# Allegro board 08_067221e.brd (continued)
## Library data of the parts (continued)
U10 = ADMAX16823: User Part Number: UPN; Tolerance: N/A; alternate symbols: (TSSOP16_5X4_4_PAD2_85X2_85); part number: ADMAX16823_SM-MAX16823AUE+,E055203,TSSOP16_5X4_4_PAD2_85X2_85; tolerance: N/A
U11-U14 = ICT3902: Tolerance: N/A; User Part Number: UPN; alternate symbols: (LGA_CAV5_MEMS); part number: ICT3902_SM-MMICT3902-00-012,E056497,LGA_CAV5_MEMS; tolerance: N/A
U15 U21 = IC24XX512: Tolerance: N/A; User Part Number: UPN; alternate symbols: (SO8); part number: IC24XX512_SM-24AA512T-I/SN,E035973,SO8; tolerance: N/A
U16 = ADLT3502: User Part Number: UPN; Tolerance: N/A; alternate symbols: (DFN8_2X2_PAD1_37X0_64); part number: ADLT3502_SM-LT3502AEDC#TRMPBF,E035029,DFN8_2X2_PAD1_37X0_64; tolerance: N/A
U19 = ADP2360: Tolerance: N/A; User Part Number: UPN; alternate symbols: (DFN8_3X3_PAD2_44X1_6); part number: ADP2360_SM-ADP2360ACPZ,E019461,DFN8_3X3_PAD2_44X1_6; tolerance: N/A
U20 = ADMAX22503E: Tolerance: N/A; User Part Number: UPN; alternate symbols: (SO14NB-2); part number: ADMAX22503E_SM-MAX22503EASD+,E055928,SO14NB-2; tolerance: N/A
U28 = 7404_V6: User Part Number: UPN; Tolerance: N/A; alternate symbols: (SOT23-5L-2); part number: 7404_V6_SM-SN74LVC1G04DBVR,E030862,SOT23-5L-2; tolerance: N/A
Y1 = XTALOSC4P_V2: Tolerance: N/A; User Part Number: UPN; alternate symbols: (YSML126W98H47); part number: XTALOSC4P_V2_SM-24.576MEGHZ,E058822,YSML126W98H47; tolerance: N/A

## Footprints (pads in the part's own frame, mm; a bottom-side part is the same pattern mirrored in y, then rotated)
C0402
  rect 0.584x0.66 smd: 1(-0.5,0) 2(0.5,0)
C0603
  rect 0.94x0.991 smd: 1(-0.8,0) 2(0.8,0)
C0603#2
  rect 0.762x0.889 smd: 1(-0.7,0) 2(0.7,0)
C0805H53
  rect 1.295x1.6 smd: 1(-0.953,0) 2(0.953,0)
C0805H60
  rect 1.295x1.6 smd: 1(-0.953,0) 2(0.953,0)
C1206
  rect 1.143x1.803 smd: 1(-1.5,0) 2(1.5,0)
C1206H71
  rect 1.6x2.007 smd: 1(-1.397,0) 2(1.397,0)
C1210-2
  rect 1.092x2.057 smd: 1(-1.646,0) 2(1.646,0)
C1812H110
  rect 1.905x3.429 smd: 1(-1.956,0) 2(1.956,0)
CAPSML169W169H217
  rect 2.591x1.6 smd: N(1.796,0) P(-1.796,0)
CN3MN2510-6002RB
  rect 1.524x1.524 hole 1.016: 1(0,0)
  round 1.524 hole 1.016: 2(0,2.54) 3(2.54,0) 4(2.54,2.54) 5(5.08,0) 6(5.08,2.54) 7(7.62,0) 8(7.62,2.54) 9(10.16,0) 10(10.16,2.54)
CNBERG2X16H330LD36
  rect 1.651x1.651 hole 1.143: 1(0,0)
  round 1.651 hole 1.143: 2(0,2.54) 3(2.54,0) 4(2.54,2.54) 5(5.08,0) 6(5.08,2.54) 7(7.62,0) 8(7.62,2.54) 9(10.16,0) 10(10.16,2.54) 11(12.7,0) 12(12.7,2.54) 13(15.24,0) 14(15.24,2.54) 15(17.78,0) 16(17.78,2.54) 17(20.32,0) 18(20.32,2.54) 19(22.86,0) 20(22.86,2.54) 21(25.4,0) 22(25.4,2.54) 23(27.94,0) 24(27.94,2.54) 25(30.48,0) 26(30.48,2.54) 27(33.02,0) 28(33.02,2.54) 29(35.56,0) 30(35.56,2.54) 31(38.1,0) 32(38.1,2.54)
CNCLIFF_FCR684208R
  round 2.21 hole 1.702 unplated: (-0.26,5.1) (5.34,5.1)
  round 1.651 hole 1.143: (0,2.6) (5.08,2.6)
  rect 1.397x1.397 hole 0.889: 1(0,0)
  round 1.397 hole 0.889: 2(2.54,0) 3(5.08,0)
CNCLIFF_FCR684208T
  round 2.21 hole 1.702 unplated: (-0.26,5.1) (5.34,5.1)
  round 1.651 hole 1.143: (0,2.6) (5.08,2.6)
  rect 1.397x1.397 hole 0.889: 1(0,0)
  round 1.397 hole 0.889: 2(2.54,0) 3(5.08,0)
CNCUI-PJ-102A_SLOTPAD
  round 2.413 hole 1.905: 1(0,0) 2(6,0) 3(3,4.7)
CNCUIRCJ-01
  rect 2.21x2.21 hole 1.702: 1(0,0)
  round 3.175 hole 2.667: 2(-5,0) 3(0,4.5) 4(5,0)
CNCUISJ1-3525NG
  oval 1.295x2.007 hole 0.787x1.499: 1(0,0)
  oval 2.007x1.295 hole 1.499x0.787: 2(5,-5) 3(5,5) 4(5,-2.5) 5(5,2.5)
CNSAMTEC2X5H338LD36
  rect 1.651x1.651 hole 1.143: 1(0,0)
  round 1.651 hole 1.143: 2(0,2.54) 3(2.54,0) 4(2.54,2.54) 5(5.08,0) 6(5.08,2.54) 7(7.62,0) 8(7.62,2.54) 9(10.16,0) 10(10.16,2.54)
CNSAMTECLSS-150-01-X-DV-A
  round 1.016 hole 0.889 unplated: (-16.625,-1.1) (16.625,-1.1)
  rect 0.406x1.6 smd: 1(-15.557,1.8) 2(-15.557,-1.8) 3(-14.922,1.8) 4(-14.922,-1.8) 5(-14.287,1.8) 6(-14.287,-1.8) 7(-13.652,1.8) 8(-13.652,-1.8) 9(-13.018,1.8) 10(-13.018,-1.8) 11(-12.383,1.8) 12(-12.383,-1.8) 13(-11.748,1.8) 14(-11.748,-1.8) 15(-11.113,1.8) 16(-11.113,-1.8) 17(-10.477,1.8) 18(-10.477,-1.8) 19(-9.842,1.8) 20(-9.842,-1.8) 21(-9.207,1.8) 22(-9.207,-1.8) 23(-8.572,1.8) 24(-8.572,-1.8) 25(-7.938,1.8) 26(-7.938,-1.8) 27(-7.303,1.8) 28(-7.303,-1.8) 29(-6.668,1.8) 30(-6.668,-1.8) 31(-6.032,1.8) 32(-6.032,-1.8) 33(-5.397,1.8) 34(-5.397,-1.8) 35(-4.763,1.8) 36(-4.763,-1.8) 37(-4.128,1.8) 38(-4.128,-1.8) 39(-3.493,1.8) 40(-3.493,-1.8) 41(-2.857,1.8) 42(-2.857,-1.8) 43(-2.223,1.8) 44(-2.223,-1.8) 45(-1.587,1.8) 46(-1.587,-1.8) 47(-0.953,1.8) 48(-0.953,-1.8) 49(-0.318,1.8) 50(-0.318,-1.8) 51(0.318,1.8) 52(0.318,-1.8) 53(0.953,1.8) 54(0.953,-1.8) 55(1.587,1.8) 56(1.587,-1.8) 57(2.223,1.8) 58(2.223,-1.8) 59(2.857,1.8) 60(2.857,-1.8) 61(3.493,1.8) 62(3.493,-1.8) 63(4.128,1.8) 64(4.128,-1.8) 65(4.763,1.8) 66(4.763,-1.8) 67(5.397,1.8) 68(5.397,-1.8) 69(6.032,1.8) 70(6.032,-1.8) 71(6.668,1.8) 72(6.668,-1.8) 73(7.303,1.8) 74(7.303,-1.8) 75(7.938,1.8) 76(7.938,-1.8) 77(8.572,1.8) 78(8.572,-1.8) 79(9.207,1.8) 80(9.207,-1.8) 81(9.842,1.8) 82(9.842,-1.8) 83(10.477,1.8) 84(10.477,-1.8) 85(11.113,1.8) 86(11.113,-1.8) 87(11.748,1.8) 88(11.748,-1.8) 89(12.383,1.8) 90(12.383,-1.8) 91(13.018,1.8) 92(13.018,-1.8) 93(13.652,1.8) 94(13.652,-1.8) 95(14.287,1.8) 96(14.287,-1.8) 97(14.922,1.8) 98(14.922,-1.8) 99(15.557,1.8) 100(15.557,-1.8)
CNTHMHDR1X2L200W98H343
  rect 1.651x1.651 hole 1.143: 1(0,0)
  round 1.651 hole 1.143: 2(2.54,0)
CNTHMHDR1X3L300W98H343
  rect 1.651x1.651 hole 1.143: 1(0,0)
  round 1.651 hole 1.143: 2(2.54,0) 3(5.08,0)
CNTHMHDR1X4L400W98H343
  rect 1.651x1.651 hole 1.143: 1(0,0)
  round 1.651 hole 1.143: 2(2.54,0) 3(5.08,0) 4(7.62,0)
CNWEIDMULLER171602
  rect 1.905x1.905 hole 1.397: 1(0,0)
  round 1.905 hole 1.397: 2(5.08,0)
CPLSMSQ260H240
  rect 3.302x1.651 smd: N(-2.601,0) P(2.601,0)
CPLSMSQ512H650
  rect 5.588x2.362 smd: N(4.85,0) P(-4.85,0)
DFN8_2X2_PAD1_37X0_64
  oval 0.254x0.737 smd: 1(-0.675,-0.888) 2(-0.225,-0.888) 3(0.225,-0.888) 4(0.675,-0.888) 5(0.675,0.888) 6(0.225,0.888) 7(-0.225,0.888) 8(-0.675,0.888)
  rect 1.372x0.635 smd: PAD(0,0)
DFN8_3X3_PAD2_44X1_6
  oval 0.356x0.787 smd: 1(-0.975,-1.5) 2(-0.325,-1.5) 3(0.325,-1.5) 4(0.975,-1.5) 5(0.975,1.5) 6(0.325,1.5) 7(-0.325,1.5) 8(-0.975,1.5)
  rect 2.438x1.6 smd: PAD(0,0)
DFN10_3X3_PAD2_38X1_65_05-08-1699
  oval 0.254x0.889 smd: 1(-1,-1.555) 2(-0.5,-1.555) 3(0,-1.555) 4(0.5,-1.555) 5(1,-1.555) 6(1,1.555) 7(0.5,1.555) 8(0,1.555) 9(-0.5,1.555) 10(-1,1.555)
  rect 2.388x1.651 smd: 11(0,0)
FLSML154W98H98
  rect 1.041x0.61 smd: 1(-1.521,0.505) 2(-1.521,-0.505) 3(1.521,-0.505) 4(1.521,0.505)
L0402-3
  rect 0.457x0.508 smd: 1(-0.479,0) 2(0.479,0)
L0603
  rect 0.94x0.991 smd: 1(-0.8,0) 2(0.8,0)
L0603-2
  rect 0.991x1.245 smd: 1(-0.787,0) 2(0.787,0)
L0805H57
  rect 0.914x1.372 smd: 1(-0.902,0) 2(0.902,0)
LED0603
  rect 0.965x0.762 smd: A(0.8,0) C(-0.8,0)
LED0805
  rect 1.245x1.092 smd: A(1.172,0) C(-1.172,0)
LEDCMD28-21B
  rect 1.524x0.762 smd: A(1.778,0)
  rect 1.524x1.016 smd: C(-1.778,0)
LEDSMSQ134H114
  rect 0.711x1.6 smd: 1(-1.061,-1.7) 2(0,-1.7) 3(1.061,-1.7) 4(1.061,1.7) 5(0,1.7) 6(-1.061,1.7)
LGA_CAV5_MEMS
  round 0.635 hole 0.508 unplated: (0.71,0)
  rect 0.533x0.737 smd: 1(-1.364,-0.837) 2(-0.542,-0.837) 4(-0.542,0.837) 5(-1.364,0.837)
  custom 0.407x0.407 smd: 3(0.71,-0.65)
LQFP64
  rect 0.254x1.651 smd: 1(-3.75,-5.675) 2(-3.25,-5.675) 3(-2.75,-5.675) 4(-2.25,-5.675) 5(-1.75,-5.675) 6(-1.25,-5.675) 7(-0.75,-5.675) 8(-0.25,-5.675) 9(0.25,-5.675) 10(0.75,-5.675) 11(1.25,-5.675) 12(1.75,-5.675) 13(2.25,-5.675) 14(2.75,-5.675) 15(3.25,-5.675) 16(3.75,-5.675) 33(3.75,5.675) 34(3.25,5.675) 35(2.75,5.675) 36(2.25,5.675) 37(1.75,5.675) 38(1.25,5.675) 39(0.75,5.675) 40(0.25,5.675) 41(-0.25,5.675) 42(-0.75,5.675) 43(-1.25,5.675) 44(-1.75,5.675) 45(-2.25,5.675) 46(-2.75,5.675) 47(-3.25,5.675) 48(-3.75,5.675)
  rect 1.651x0.254 smd: 17(5.675,-3.75) 18(5.675,-3.25) 19(5.675,-2.75) 20(5.675,-2.25) 21(5.675,-1.75) 22(5.675,-1.25) 23(5.675,-0.75) 24(5.675,-0.25) 25(5.675,0.25) 26(5.675,0.75) 27(5.675,1.25) 28(5.675,1.75) 29(5.675,2.25) 30(5.675,2.75) 31(5.675,3.25) 32(5.675,3.75) 49(-5.675,3.75) 50(-5.675,3.25) 51(-5.675,2.75) 52(-5.675,2.25) 53(-5.675,1.75) 54(-5.675,1.25) 55(-5.675,0.75) 56(-5.675,0.25) 57(-5.675,-0.25) 58(-5.675,-0.75) 59(-5.675,-1.25) 60(-5.675,-1.75) 61(-5.675,-2.25) 62(-5.675,-2.75) 63(-5.675,-3.25) 64(-5.675,-3.75)
LSML213W201H59
  rect 1.397x2.794 smd: 1(-2.199,0) 2(2.199,0)
LSMSQ157H122
  rect 0.965x3.708 smd: 1(-1.181,0) 2(1.181,0)
LSMSQ189H118_A
  custom 0.502x0.502 smd: 1(-2.255,0) 2(2.255,0)
LXT0805
  rect 1.194x1.194 smd: A(1.041,0) C(-1.041,0)
MRJE73-188-00XXX
  round 2.311 hole 1.803 unplated: (-2.17,-0.33) (9.31,-0.33)
  rect 1.397x1.397 hole 0.889: 1(0,0)
  round 1.397 hole 0.889: 2(1.02,-1.78) 3(2.04,0) 4(3.06,-1.78) 5(4.08,0) 6(5.1,-1.78) 7(6.12,0) 8(7.14,-1.78)
  round 1.6 hole 1.092: 9(-3.44,3.27) 10(-0.9,3.27) 11(8.04,3.27) 12(10.58,3.27)
  oval 1.295x2.515 hole 0.787x2.007: 13(-4.43,-4.68) 14(11.57,-4.68)
POWERDI5060-8
  rect 0.61x1.27 smd: 1(-1.905,-2.67) 2(-0.635,-2.67) 3(0.635,-2.67) 4(1.905,-2.67)
  custom 1.13x1.13 smd: 5(1.905,2.797)
  round 0.127 smd: 6(0.635,2.67) 7(-0.635,2.67) 8(-1.905,2.67)
QFN48_7X7_PAD4_1X4_1
  round 2.718 hole 1.702 unplated: (-4.863,4.863) (-4.863,-4.863) (4.863,4.863) (4.863,-4.863)
  round 1.092 hole 0.838 unplated: (-2.863,4.863) (1.863,-4.863)
  oval 0.305x0.889 smd: 1(-2.75,-3.2) 2(-2.25,-3.2) 3(-1.75,-3.2) 4(-1.25,-3.2) 5(-0.75,-3.2) 6(-0.25,-3.2) 7(0.25,-3.2) 8(0.75,-3.2) 9(1.25,-3.2) 10(1.75,-3.2) 11(2.25,-3.2) 12(2.75,-3.2) 25(2.75,3.7) 26(2.25,3.7) 27(1.75,3.7) 28(1.25,3.7) 29(0.75,3.7) 30(0.25,3.7) 31(-0.25,3.7) 32(-0.75,3.7) 33(-1.25,3.7) 34(-1.75,3.7) 35(-2.25,3.7) 36(-2.75,3.7)
  oval 0.889x0.305 smd: 13(3.45,-2.5) 14(3.45,-2) 15(3.45,-1.5) 16(3.45,-1) 17(3.45,-0.5) 18(3.45,0) 19(3.45,0.5) 20(3.45,1) 21(3.45,1.5) 22(3.45,2) 23(3.45,2.5) 24(3.45,3) 37(-3.45,3) 38(-3.45,2.5) 39(-3.45,2) 40(-3.45,1.5) 41(-3.45,1) 42(-3.45,0.5) 43(-3.45,0) 44(-3.45,-0.5) 45(-3.45,-1) 46(-3.45,-1.5) 47(-3.45,-2) 48(-3.45,-2.5)
  rect 4.089x4.089 smd: PAD(0,0.25)
QFN72_10X10_PAD5_3X5_3
  oval 0.305x0.838 smd: 1(-4.25,-4.95) 2(-3.75,-4.95) 3(-3.25,-4.95) 4(-2.75,-4.95) 5(-2.25,-4.95) 6(-1.75,-4.95) 7(-1.25,-4.95) 8(-0.75,-4.95) 9(-0.25,-4.95) 10(0.25,-4.95) 11(0.75,-4.95) 12(1.25,-4.95) 13(1.75,-4.95) 14(2.25,-4.95) 15(2.75,-4.95) 16(3.25,-4.95) 17(3.75,-4.95) 18(4.25,-4.95) 37(4.25,4.95) 38(3.75,4.95) 39(3.25,4.95) 40(2.75,4.95) 41(2.25,4.95) 42(1.75,4.95) 43(1.25,4.95) 44(0.75,4.95) 45(0.25,4.95) 46(-0.25,4.95) 47(-0.75,4.95) 48(-1.25,4.95) 49(-1.75,4.95) 50(-2.25,4.95) 51(-2.75,4.95) 52(-3.25,4.95) 53(-3.75,4.95) 54(-4.25,4.95)
  oval 0.838x0.305 smd: 19(4.95,-4.25) 20(4.95,-3.75) 21(4.95,-3.25) 22(4.95,-2.75) 23(4.95,-2.25) 24(4.95,-1.75) 25(4.95,-1.25) 26(4.95,-0.75) 27(4.95,-0.25) 28(4.95,0.25) 29(4.95,0.75) 30(4.95,1.25) 31(4.95,1.75) 32(4.95,2.25) 33(4.95,2.75) 34(4.95,3.25) 35(4.95,3.75) 36(4.95,4.25) 55(-4.95,4.25) 56(-4.95,3.75) 57(-4.95,3.25) 58(-4.95,2.75) 59(-4.95,2.25) 60(-4.95,1.75) 61(-4.95,1.25) 62(-4.95,0.75) 63(-4.95,0.25) 64(-4.95,-0.25) 65(-4.95,-0.75) 66(-4.95,-1.25) 67(-4.95,-1.75) 68(-4.95,-2.25) 69(-4.95,-2.75) 70(-4.95,-3.25) 71(-4.95,-3.75) 72(-4.95,-4.25)
  rect 5.309x5.309 smd: PAD(0,0)
R0402
  rect 0.635x0.737 smd: 1(-0.5,0) 2(0.5,0)
R0603
  rect 0.787x0.991 smd: 1(-0.85,0) 2(0.85,0)
R0805
  rect 1.041x1.397 smd: 1(-0.95,0) 2(0.95,0)
R1206
  rect 1.041x1.753 smd: 1(-1.5,0) 2(1.5,0)
R1206-2
  rect 1.397x1.803 smd: 1(-1.298,0) 2(1.298,0)
R1210
  rect 1.575x2.692 smd: 1(-1.397,0) 2(1.397,0)
SC70-5
  rect 0.406x0.813 smd: 1(-0.65,-0.89) 2(0,-0.89) 3(0.65,-0.89) 4(0.65,0.89) 5(-0.65,0.89)
SMA
  rect 2.032x2.032 smd: A(1.994,0) C(-1.994,0)
SO4H96
  rect 0.66x1.956 smd: 1(-0.635,-3.083) 2(0.635,-3.083) 3(0.635,3.083) 4(-0.635,3.083)
SO8
  rect 0.61x2.184 smd: 1(-1.905,-2.54) 2(-0.635,-2.54) 3(0.635,-2.54) 4(1.905,-2.54) 5(1.905,2.54) 6(0.635,2.54) 7(-0.635,2.54) 8(-1.905,2.54)
SO8NB-5
  rect 0.635x1.829 smd: 1(-1.905,-2.591) 2(-0.635,-2.591) 3(0.635,-2.591) 4(1.905,-2.591) 5(1.905,2.591) 6(0.635,2.591) 7(-0.635,2.591) 8(-1.905,2.591)
SO14NB-2
  rect 0.635x1.829 smd: 1(-3.81,-2.591) 2(-2.54,-2.591) 3(-1.27,-2.591) 4(0,-2.591) 5(1.27,-2.591) 6(2.54,-2.591) 7(3.81,-2.591) 8(3.81,2.591) 9(2.54,2.591) 10(1.27,2.591) 11(0,2.591) 12(-1.27,2.591) 13(-2.54,2.591) 14(-3.81,2.591)
SO16NB-2
  rect 0.635x1.829 smd: 1(-4.445,-2.591) 2(-3.175,-2.591) 3(-1.905,-2.591) 4(-0.635,-2.591) 5(0.635,-2.591) 6(1.905,-2.591) 7(3.175,-2.591) 8(4.445,-2.591) 9(4.445,2.591) 10(3.175,2.591) 11(1.905,2.591) 12(0.635,2.591) 13(-0.635,2.591) 14(-1.905,2.591) 15(-3.175,2.591) 16(-4.445,2.591)
SOD123F
  rect 1.194x1.194 smd: A(1.403,0) C(-1.403,0)
SOD123FL
  rect 0.914x1.219 smd: A(1.638,0) C(-1.638,0)
SOT23-5L-2
  rect 0.61x1.194 smd: 1(-0.95,-1.15) 2(0,-1.15) 3(0.95,-1.15) 4(0.95,1.15) 5(-0.95,1.15)
SOT143A
  rect 1.092x1.27 smd: 1(-0.76,-1)
  rect 0.711x1.27 smd: 2(0.96,-1) 3(0.96,1) 4(-0.96,1)
SOT363H43
  rect 0.432x0.61 smd: 1(-0.65,-0.95) 2(0,-0.95) 3(0.65,-0.95) 4(0.65,0.95) 5(0,0.95) 6(-0.65,0.95)
SWSML165W110H75-G
  rect 0.889x0.991 smd: 1(-2.044,-0.795) 2(-2.044,0.795) 3(2.044,0.795) 4(2.044,-0.795)
  rect 1.702x0.559 smd: 5(0,-1.439)
SWSML354W142H217
  rect 1.194x2.515 smd: 1(-2.489,-2.743) 2(0,-2.743) 3(2.489,-2.743) 4(-2.489,2.743) 5(0,2.743) 6(2.489,2.743)
TO252
  rect 1.6x2.997 smd: 1(-2.3,-4.063) 3(2.3,-4.063)
  rect 6.706x6.706 smd: 2(0,2.589)
TPC65D45
  round 1.651 hole 1.143: 1(0,0)
TSML185W127H114_A
  rect 1.194x0.406 smd: 1(-1.99,-1.35) 2(-1.99,-0.7) 6(1.99,0.7) 7(1.99,1.35)
  custom 0.108x0.108 smd: 3(-2.371,1.35) 4(-1.606,1.35)
  rect 1.194x0.508 smd: 5(1.99,-1.305)
TSML387W323H220
  rect 1.016x2.54 smd: 1(-3.01,-5.08) 2(-1.003,-5.08) 3(1.003,-5.08) 4(3.01,-5.08) 5(3.01,5.08) 6(1.003,5.08) 7(-1.003,5.08) 8(-3.01,5.08)
TSSOP16_5X4_4_PAD2_85X2_85
  rect 0.381x1.27 smd: 1(-2.275,-2.82) 2(-1.625,-2.82) 3(-0.975,-2.82) 4(-0.325,-2.82) 5(0.325,-2.82) 6(0.975,-2.82) 7(1.625,-2.82) 8(2.275,-2.82) 9(2.275,2.82) 10(1.625,2.82) 11(0.975,2.82) 12(0.325,2.82) 13(-0.325,2.82) 14(-0.975,2.82) 15(-1.625,2.82) 16(-2.275,2.82)
  rect 2.845x2.845 smd: PAD(0,0)
unnamed#2
  round 4.445 hole 3.175 unplated: (0,0)
YSML126W98H47
  rect 1.397x1.194 smd: 1(-1.2,-0.95) 2(1.2,-0.95) 3(1.2,0.95) 4(-1.2,0.95)

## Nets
DGND: C1.1 C2.1 C3.1 C4.2(N2) C5.1 C6.1 C7.1 C8.1 C9.1 C10.1 C11.1 C12.1 C13.1 C14.1 C15.1 C16.1 C17.1 C18.1 C20.1 C21.1 C22.1 C23.2(N2) C24.1 C25.1 C26.1 C27.1 C28.1 C29.1 C31.1 C32.1 C33.1 C34.1 C35.2(N2) C36.1 C37.1 C38.1 C39.2(N2) C40.1 C41.2(N2) C42.1 C43.1 C46.1 C47.N(N2) C48.1 C49.1 C50.2(N2) C51.2(N2) C52.1 C55.1 C56.1 C57.1 C59.1 C61.1 C62.1 C64.2(N2) C65.1 C66.1 C67.2(N2) C69.1 C71.1 C72.2(N2) C73.1 C74.1 C75.1 C76.1 C77.1 C78.1 C79.1 C80.2(N2) C81.1 C82.1 C83.1 C84.1 C85.1 C87.1 C88.1 C89.1 C92.1 C93.1 C94.2(N2) C95.1 C96.1 C97.1 C100.1 C101.1 C102.1 C103.N(N2) C104.N(N2) C105.1 C106.1 C107.1 C108.1 C109.1 C110.1 C111.1 C112.1 C114.1 C116.2(N2) C118.1 C119.1 C120.1 C121.1 C122.1 C123.1 C124.1 C125.1 C126.1 C127.1 C128.1 C129.1 C131.1 C132.N(N2) C133.1 C135.1 C136.1 C137.1 C138.1 C140.1 C141.2(N2) C145.1 C146.1 C148.2(N2) C149.1 C150.2(N2) C151.2(N2) C152.2(N2) C153.1 C154.1 C156.1 C159.1 C161.1 C162.1 C163.1 C165.1 C168.1 C169.2(N2) C170.2(N2) C171.2(N2) C172.1 C173.1 C175.1 C176.1 C177.1 C178.1 C179.1 D3.A(P) D4.A(P) D8.1 D8.4 D9.1 D9.4 D10.A(P) DS2.C DS3.C DS4.C DS5.C DS7.C DS8.C DS9.C DS10.C DS11.C L6.1 P1.2 P1.3(N3) P2.2(N2) P4.2 P6.1 P8.9(N9) P8.10 P10.1 P10.6 P10.8 P10.13 P10.14(SH2) P15.2 P15.4 P15.6 P15.8 P15.10 P15.12 P15.14 P15.16 P15.18(N9) P15.20 P15.22 P15.24 P15.26 P15.28 P15.30 P15.32 P28.1 P29.1 P30.10 P32.1 P32.2 P32.5 P32.6 P32.9 P32.10 P32.13 P32.14 P32.17 P32.18(N9) P32.21 P32.22 P32.25 P32.26 P32.29 P32.30 P32.33 P32.34 P32.37 P32.38 P32.41 P32.42 P32.45 P32.46 P32.49 P32.50 P32.53 P32.54 P32.57 P32.58 P32.61 P32.62 P32.65 P32.66 P32.69 P32.70 P32.73 P32.74 P32.77 P32.78 P32.81 P32.82 P32.85 P32.89 P32.90 P32.91 P32.92 P32.94 R16.1 R21.1 R23.1 R24.1 R28.2(N2) R30.1 R31.1 R31.2(N2) R42.1 R72.1 R73.1 R80.2(N2) R82.2(N2) R85.2(N2) R93.1 R96.1 R96.2(N2) R110.1 R112.1 R112.2(N2) R128.1 R133.1 R135.1 R143.1 R144.1 R145.1 R146.1 R147.1 R149.1 R150.1 R151.1 R152.1 R153.1 R156.1 R159.1 R163.1 R164.1 R168.2(N2) R170.1 R176.2(N2) R178.1 R179.1 R184.1 R190.1 R215.1 R216.1 R244.1 R246.1 R248.1 R249.2(N2) R250.1 SW1.1 SW1.4 SW1.5(N5) T2.6 T2.7 T3.6 T3.7 TP2.1(N1) TP9.1(N1) TP12.1(N1) TP14.1(N1) TP21.1(N1) U1.3 U2.1 U3.5 U3.11 U4.1 U4.3 U5.4(-VS) U6.1 U6.6 U6.14 U6.17 U6.19 U6.25 U6.36 U6.37 U6.54 U6.55 U6.72 U6.PAD U7.1 U7.4 U7.16 U7.23(VSUPPLY) U7.24 U7.25 U7.33 U7.44 U7.46 U7.48 U8.8 U9.1 U9.4 U9.10 U9.20 U9.26(VSS) U9.30 U9.32 U9.38 U9.44 U9.PAD U10.12 U10.PAD U11.3 U12.2 U12.3 U13.3 U14.2 U14.3 U15.4 U16.5 U16.PAD U17.4(-VS) U18.4(-VS) U19.6 U19.PAD U20.3 U20.6 U20.7 U21.4 U24.3 U25.3 U26.3 U27.3 U28.3 Y1.2
GND_ISO: C99.1 C102.2(N2) P22.1 P22.6 P22.8 R65.1 R247.2(N2)
GND_SHIELD_A: C99.2(N2) P22.13 P22.14(SH2) TP4.1(N1)
VDD_3V3: C1.2(N2) C4.1 C5.2(N2) C26.2(N2) C27.2(N2) C56.2(N2) C60.1 C66.2(N2) C67.1 C82.2(N2) C94.1 C95.2(N2) C97.2(N2) C107.2(N2) C108.2(N2) C109.2(N2) C110.2(N2) C111.2(N2) C119.2(N2) C124.2(N2) C129.2(N2) C145.2(N2) C146.2(N2) C154.2(N2) C156.2(N2) C159.2(N2) C163.2(N2) C169.1 C170.1 C171.1 C172.2(N2) C175.2(N2) C176.2(N2) C179.2(N2) D8.2 D8.5(C1) D9.2 D9.5(C1) DS1.A(P) E1.1 E2.1 E6.1 E9.2(N2) E12.2(N2) E16.2(N2) E18.2(N2) JP47.1 P4.3 P6.2 P8.7 Q3.3(E) R2.1 R5.1 R9.1 R12.2(N2) R15.2(N2) R19.2(N2) R22.2(N2) R26.2(N2) R33.2(N2) R39.2(N2) R53.2(N2) R74.2(N2) R95.2(N2) R101.1 R107.1 R115.2(N2) R117.1 R118.1 R119.1 R122.2(N2) R126.2(N2) R137.2(N2) R139.2(N2) R142.2(N2) R148.2(N2) R161.2(N2) R166.2(N2) R174.2(N2) R175.2(N2) R180.2(N2) R185.2(N2) R186.2(N2) R187.1 R231.1 R238.2(N2) R243.2(N2) TP24.1(N1) U1.5 U2.4(VCC) U4.5(VCC) U5.8 U6.2 U6.18 U6.38 U6.56 U7.5 U7.17 U7.32 U7.45 U7.51 U7.62 U9.46 U15.8 U17.8 U18.8 U20.4 U20.13 U20.14 U24.5 U25.5 U26.5(VCC) U27.5(VCC) U28.5(VCC) Y1.4(VDD)
VDD_5V: C29.2(N2) C122.2(N2) D2.C D10.C L1.2(N2) P10.9 R170.2(N2) TP3.1(N1)
VDD_5V_BPORT: C120.2(N2) D2.A(P) E3.2(N2) R36.2(N2) R165.2(N2)
1452_RESET: C88.2(N2) R6.1 R107.2(N2) U6.24
AD243X_ADR1_SS: P15.23 P32.79 R100.1 R195.1
AD243X_AN: C30.2(N2) L2.2(N2) L4.1 U9.28
AD243X_AP: C30.1 L3.1 L5.1 U9.29
AD243X_BCLK: C10.2(N2) C151.1 JP1.4(N4) P15.1 P32.3 R45.2(N2) R62.2(N2) R172.2(N2) R241.1
AD243X_BCM: C13.2(N2) C14.2(N2) U9.35
AD243X_BN: C45.1 L9.1 L11.1 U9.34
AD243X_BP: C45.2(N2) L8.2(N2) L10.1 U9.33
AD243X_DRX0: C11.2(N2) JP6.1 P15.7 P32.11 R47.2(N2) R57.2(N2)
AD243X_DRX1: C12.2(N2) JP9.1 P15.9 P32.15 R48.2(N2)
AD243X_GPIO7: JP1.2 R14.1 R189.1 U4.2
AD243X_IOVDD: C22.2(N2) C40.2(N2) E1.2(N2) R7.2(N2) TP10.1(N1) U9.11 U9.21
AD243X_IRQ: P15.29 P32.59 R38.2(N2) R69.1 R118.2(N2) U9.24
AD243X_ISENSEP: Q4.5 Q4.6 Q4.7 Q4.8 R182.1 U9.42
AD243X_MISO: R86.1 R232.1
AD243X_MISO_SW: P15.19 P32.63 R92.1 R120.1
AD243X_MOSI: R97.1 R223.1
AD243X_MOSI_SW: P15.21 P32.67 R11.1 R111.1
AD243X_RESET: C173.2(N2) P23.1(N1) R3.1 R7.1 U9.25
AD243X_SCK: R106.1 R235.1
AD243X_SCK_SW: P15.17 P32.71 R113.1 R199.1
AD243X_SCL: P15.25 R35.2(N2) R70.2(N2) R122.1 U9.16
AD243X_SDA: P15.27 R55.2(N2) R126.1 R203.2(N2) U9.15
AD243X_SIO2: C141.1 P15.11 P32.19 R34.2(N2) R68.1 R81.1 R84.2(N2) R98.1
AD243X_SIO3: C64.1 P15.13 P32.23 R67.1 R114.1
AD243X_SIO4: C71.2(N2) P15.15 P32.27 R66.1 R121.1 R171.2(N2)
AD243X_SWP: C174.2(N2) Q4.4 U9.41
AD243X_SYNC: C9.2(N2) C152.1 P15.3 P32.7 R44.2(N2) R63.2(N2) R173.2(N2) R240.1
AD243X_VBUS: C46.2(N2) C101.2(N2) C103.P C104.P C114.2(N2) C132.P D5.C E11.2(N2) R18.2(N2) R32.2(N2) R154.1 R162.2(N2) R182.2(N2) TP13.1(N1) TP25.1(N1) U3.8(VOUT) U9.43 U16.1(VIN) U19.8(VIN)
AD243X_VOUT1: C123.2(N2) C126.2(N2) C128.2(N2) R169.2(N2) TP11.1(N1) U9.2 U9.3 U9.47 U9.48
AD243X_VSENSEP: R181.1 U9.40
AD1937_ADR0: R142.1 R143.2(N2) U7.30
AD1937_ADR1: R185.1 R190.2(N2) U7.35
AD1937_ASDATA1: R57.1 R71.1 R105.2(N2) TP8.1(N1)
AD1937_BCLK: C17.2(N2) R51.2(N2) R58.1 R87.1 R172.1
AD1937_CM: C83.2(N2) C112.2(N2) C137.2(N2) C138.2(N2) R43.2(N2) R60.2(N2) R61.2(N2) R124.2(N2) U7.52 U17.3 U17.5 U18.3 U18.5
AD1937_DSDATA1: C18.2(N2) R52.2(N2) R104.1 R171.1 TP7.1(N1)
AD1937_MCLKI: R91.1 R94.1 U7.2
AD1937_RESET: C162.2(N2) R134.1 R187.2(N2) U7.14
AD1937_SYNC: C16.2(N2) R50.2(N2) R59.1 R173.1 R183.1
ADAU1452_AUXADC0: P8.1 U6.8
ADAU1452_AUXADC1: P8.2 U6.9
ADAU1452_AUXADC2: P8.3 U6.10
ADAU1452_AUXADC3: P8.4 U6.11
ADAU1452_AUXADC4: P8.5 U6.12
ADAU1452_AUXADC5: P8.6 U6.13
ADAU1452_CLKOUT: C125.2(N2) R88.2(N2) R94.2(N2) TP18.1(N1)
ADAU1452_MP6: R95.1 U6.45 U25.1
ADAU1452_MP11: P8.8 U6.61
ADAU1452_SCL: R25.2(N2) R53.1 R79.2(N2) R132.2(N2) U27.2
ADAU1452_SDA: R29.2(N2) R39.1 R77.2(N2) R138.2(N2) U26.2
ADAU1452_SELFBOOT: JP2.2(N2) R93.2(N2) U6.34 U25.2
ADAU1452_SPDIFIN: R127.2(N2) R193.1 R226.2(N2)
ADAU1452_SPDIFIN_OPT: C177.2(N2) R103.2(N2) R119.2(N2) R127.1
ADAU1452_SPDIFIN_RCA: R226.1 U20.2
ADAU1452_SPDIFOUT: R116.2(N2) R227.2(N2) R228.2(N2)
ADAU1452_SPDIFOUT_OPT: C178.2(N2) P6.3(VIN) R227.1
ADAU1452_SPDIFOUT_RCA: R228.1 U20.5
ADC1LN: C133.2(N2) C134.2(N2) C142.2(N2) U7.54
ADC1LP: C134.1 C135.2(N2) C143.2(N2) U7.53
ADC1RN: C139.2(N2) C140.2(N2) C147.2(N2) U7.56
ADC1RP: C136.2(N2) C139.1 C144.2(N2) U7.55
ADP2360_EN: R154.2(N2) R159.2(N2) U19.1
ADP2360_PG: JP1.1 R125.2(N2) R161.1 U19.2
ADR1/SPISS0: JP42.1 R89.1 R177.1
ADR2/IO2/MCLK: JP38.3(N3) P15.31 P32.47 R12.1 R21.2(N2) R49.2(N2) R91.2(N2) R140.2(N2) R242.1
BCLK_IN0: R62.1 U6.57
DAC1LN: R194.1 U7.37
DAC1LP: R192.1 U7.36
DAC1RN: R212.1 U7.39
DAC1RP: R211.1 U7.38
HW_RESET: P32.55 R1.1
I2C_BUS_SWITCH: R238.1 U25.4(Y) U26.1 U27.1 U28.2
L_CH_THRU: P28.4 P29.4
LRCLK_IN0: R63.1 U6.58
LT3502_VFB: R160.2(N2) R184.2(N2) U16.3
LTC4368_SENSE: Q1.5 Q1.6 R18.1 U3.9
LTC4368_SHDN*: JP4.2 R27.2(N2)
LTC4368_WAKEUP: JP4.3(N3) Q2.3(E) R42.2(N2)
PDM_CLK: JP1.3 R157.2(N2)
PDM_DATA0: C84.2(N2) JP6.3(N3) R130.2(N2) R131.2(N2)
PDM_DATA1: C100.2(N2) JP9.3(N3) R141.2(N2) R158.2(N2)
R_CH_THRU: P28.5(N5) P29.5(N5)
SDATA_OUT0: R47.1 U6.41
SDATA_OUT1: R48.1 U6.44
SLAVE_ADDR0: R178.2(N2) U6.33
SLAVE_ADDR1: R179.2(N2) U6.32
UNNAMED_3_AD243XW_I149_ACM: C31.2(N2) C32.2(N2) U9.27
UNNAMED_3_AD243XW_I149_ADR1: R22.1 R135.2(N2) R195.2(N2) U9.22
UNNAMED_3_AD243XW_I149_ADR2: R242.2(N2) U9.23
UNNAMED_3_AD243XW_I149_BCLK: R241.2(N2) U9.9
UNNAMED_3_AD243XW_I149_GPIO7: R14.2(N2) U9.14
UNNAMED_3_AD243XW_I149_ISENSEN: R72.2(N2) U9.36 U9.37
UNNAMED_3_AD243XW_I149_MISO: R120.2(N2) U9.17
UNNAMED_3_AD243XW_I149_MOSI: R11.2(N2) U9.18
UNNAMED_3_AD243XW_I149_SCK: R199.2(N2) U9.19
UNNAMED_3_AD243XW_I149_SIO0: C41.1 JP6.2 U9.5
UNNAMED_3_AD243XW_I149_SIO1: R54.2(N2) U9.6
UNNAMED_3_AD243XW_I149_SIO2: R98.2(N2) U9.7
UNNAMED_3_AD243XW_I149_SIO3: R114.2(N2) U9.12
UNNAMED_3_AD243XW_I149_SIO4: R121.2(N2) U9.13
UNNAMED_3_AD243XW_I149_SWN: R73.2(N2) U9.39
UNNAMED_3_AD243XW_I149_SYNC: R240.2(N2) U9.8
UNNAMED_3_CAP_I12_N1: C51.1 JP9.2 R54.1
UNNAMED_3_DIOLED_I84_P: DS10.A(P) R34.1
UNNAMED_3_DIOLED_I208_P: DS9.A(P) R38.1
UNNAMED_3_IC24XX512_I97_A0: R147.2(N2) R148.1 U15.1
UNNAMED_3_IC24XX512_I97_A1: R139.1 R146.2(N2) U15.2
UNNAMED_3_IC24XX512_I97_A2: R133.2(N2) R137.1 U15.3
UNNAMED_3_IC24XX512_I97_SCL: R35.1 U15.6
UNNAMED_3_IC24XX512_I97_SDA: R203.1 U15.5
UNNAMED_3_IC24XX512_I97_WP: R243.1 R244.2(N2) U15.7(WP)
UNNAMED_4_CAP_I21_N1: C70.1 FL2.4(N4) R41.2(N2)
UNNAMED_4_CAP_I21_N2: C70.2(N2) T1.2
UNNAMED_4_CAP_I24_N2: C65.2(N2) C80.1 R40.1 R41.1
UNNAMED_4_CAP_I25_N1: C68.1 FL2.3 R40.2(N2)
UNNAMED_4_CAP_I25_N2: C68.2(N2) T1.1
UNNAMED_4_CAP_I67_N2: C33.2(N2) L2.1 L3.2(N2)
UNNAMED_4_CAP_I73_N1: C35.1 FL2.1 L5.2(N2)
UNNAMED_4_CAP_I74_N2: C34.2(N2) FL2.2 L4.2(N2)
UNNAMED_4_CAP_I91_N1: C72.1 T1.5
UNNAMED_4_CAP_I138_N2: C44.2(N2) C98.2(N2) R65.2(N2)
UNNAMED_4_CAP_I139_N1: C98.1 R46.2(N2) T1.3 TP26.1(N1)
UNNAMED_4_MODRJE7318800XXX_I171_2: P22.2 P22.3 P22.7 P22.11
UNNAMED_4_MODRJE7318800XXX_I171_4: P22.4 T1.6
UNNAMED_4_MODRJE7318800XXX_I171_5: P22.5 T1.7(SEC_2)
UNNAMED_4_MODRJE7318800XXX_I171_LED1C: P22.12 R247.1
UNNAMED_4_TRANOPTO4PV2_I78_C: C44.1 Q2.2 T1.4
UNNAMED_5_CAP_I12_N1: C24.2(N2) C39.1 R56.1 R78.1
UNNAMED_5_CAP_I100_N2: C49.2(N2) FL1.2 L10.2(N2)
UNNAMED_5_CAP_I102_N2: C48.2(N2) L8.1 L9.2(N2)
UNNAMED_5_CAP_I105_N1: C50.1 FL1.1 L11.2(N2)
UNNAMED_5_CAP_I116_N1: C116.1 C117.1 C174.1 D4.C D5.A(P) D6.C P10.2 P10.3 P10.7 P10.11 Q4.1 Q4.2 Q4.3(S3) R181.2(N2)
UNNAMED_5_CAP_I116_N2: C117.2(N2) R168.1
UNNAMED_5_CAP_I145_N2: C53.2(N2) L6.2(N2) P10.4
UNNAMED_5_CAP_I146_N1: C54.1 FL1.4(N4) R56.2(N2)
UNNAMED_5_CAP_I146_N2: C54.2(N2) L1.1 P10.5
UNNAMED_5_DIOSCHOTTKY_I144_P: D6.A(P) R220.1
UNNAMED_5_FLTR4PV7_I16_N3: C53.1 FL1.3 R78.2(N2)
UNNAMED_5_MODRJE7318800XXX_I184_LED1C: P10.12 R249.1
UNNAMED_5_MODRJE7318800XXX_I184_LED2C: P10.10 R248.2(N2)
UNNAMED_5_RES_I124_N1: R165.1 R166.1 R220.2(N2)
UNNAMED_7_741G125_I116_B: P32.43 U4.4
UNNAMED_7_7408V3_I90_A: R1.2(N2) R2.2(N2) U1.1
UNNAMED_7_7408V3_I100_A: U1.4(Y) U24.1
UNNAMED_7_7408V3_I100_B: C131.2(N2) R101.2(N2) R136.2(N2) U24.2
UNNAMED_7_7408V3_I100_Y: R9.2(N2) U2.3 U24.4(Y)
UNNAMED_7_ADM6315_I36_RESETN: R8.2(N2) U2.2
UNNAMED_7_CN32PODDEVEN_I115_N3: P15.5 R189.2(N2)
UNNAMED_7_CN100PV2_I48_N20: P32.39 R125.1
UNNAMED_7_CN100PV2_I48_N38: P32.75 R177.2(N2)
UNNAMED_7_CN100PV2_I56_N43: P32.86 R169.1
UNNAMED_7_CN100PV2_I56_N44: P32.88 R174.1
UNNAMED_7_DIOLED_I69_N: DS1.C R4.2(N2)
UNNAMED_7_RES_I25_N2: R3.2(N2) R4.1 R6.2(N2) R8.1 R134.2(N2)
UNNAMED_7_RES_I97_N1: R136.1 SW1.2 SW1.3
UNNAMED_8_ADAU145X_I261_AVDD: C58.2(N2) C61.2(N2) C62.2(N2) C79.2(N2) C81.2(N2) C86.1 E6.2(N2) U6.7 U6.15
UNNAMED_8_ADAU145X_I261_BCLKIN3: R87.2(N2) U6.68
UNNAMED_8_ADAU145X_I261_BCLKOUT0: R45.1 U6.40
UNNAMED_8_ADAU145X_I261_BCLKOUT1: R176.1 U6.43
UNNAMED_8_ADAU145X_I261_BCLKOUT2: R140.1 U6.48
UNNAMED_8_ADAU145X_I261_BCLKOUT3: R51.1 U6.51
UNNAMED_8_ADAU145X_I261_CLKOUT: R88.1 U6.23
UNNAMED_8_ADAU145X_I261_DVDD1: C23.1 C36.2(N2) C42.2(N2) C52.2(N2) C69.2(N2) C73.2(N2) C76.2(N2) C78.2(N2) R37.1 U6.20 U6.35 U6.53 U6.71
UNNAMED_8_ADAU145X_I261_LRCLKIN2: R81.2(N2) U6.66
UNNAMED_8_ADAU145X_I261_LRCLKIN3: R183.2(N2) U6.69
UNNAMED_8_ADAU145X_I261_LRCLKOUT0: R44.1 U6.39
UNNAMED_8_ADAU145X_I261_LRCLKOUT1: R75.1 U6.42
UNNAMED_8_ADAU145X_I261_LRCLKOUT2: R49.1 U6.47
UNNAMED_8_ADAU145X_I261_LRCLKOUT3: R50.1 U6.50
UNNAMED_8_ADAU145X_I261_MISO: R76.1 U6.30
UNNAMED_8_ADAU145X_I261_MP7: R69.2(N2) U6.46
UNNAMED_8_ADAU145X_I261_PLLFILT: C58.1 R99.1 U6.16
UNNAMED_8_ADAU145X_I261_SCLK: R64.2(N2) U6.31
UNNAMED_8_ADAU145X_I261_SCLM: R79.1 U6.28
UNNAMED_8_ADAU145X_I261_SDAM: R77.1 U6.29
UNNAMED_8_ADAU145X_I261_SDATAIN0: R66.2(N2) U6.59
UNNAMED_8_ADAU145X_I261_SDATAIN1: R67.2(N2) U6.62
UNNAMED_8_ADAU145X_I261_SDATAIN2: R68.2(N2) U6.67
UNNAMED_8_ADAU145X_I261_SDATAIN3: R71.2(N2) U6.70
UNNAMED_8_ADAU145X_I261_SDATAOUT2: R84.1 U6.49
UNNAMED_8_ADAU145X_I261_SDATAOUT3: R52.1 U6.52
UNNAMED_8_ADAU145X_I261_SPDIFIN: R193.2(N2) U6.4
UNNAMED_8_ADAU145X_I261_SPDIFOUT: R116.1 U6.5
UNNAMED_8_ADAU145X_I261_SSM: R85.1 U6.26
UNNAMED_8_ADAU145X_I261_THDM: TP17.1(N1) U6.63
UNNAMED_8_ADAU145X_I261_THDP: TP16.1(N1) U6.64
UNNAMED_8_ADAU145X_I261_VDRIVE: Q3.1 R175.1 U6.3
UNNAMED_8_ADAU145X_I261_XTALIN: JP38.2 U6.21
UNNAMED_8_CAP_I189_N2: C74.2(N2) R186.1
UNNAMED_8_CAP_I196_N2: C86.2(N2) R99.2(N2)
UNNAMED_8_CN3P_I266_N1: JP38.1 R109.2(N2)
UNNAMED_8_CN3PV16_I292_VOUT: P4.1(VOUT) R103.1
UNNAMED_8_CN10P_I309_N1: P30.1 R234.2(N2)
UNNAMED_8_CN10P_I309_N3: P30.3 R233.2(N2)
UNNAMED_8_CN10P_I309_N4: P30.4 R155.2(N2)
UNNAMED_8_CN10P_I309_N5: P30.5 R232.2(N2)
UNNAMED_8_CN10P_I309_N6: P30.6 R225.2(N2)
UNNAMED_8_CN10P_I309_N7: P30.7 R235.2(N2)
UNNAMED_8_CN10P_I309_N8: P30.8 R223.2(N2)
UNNAMED_8_CN10P_I309_N9: JP42.2(N2) P30.9(N9) R231.2(N2)
UNNAMED_8_DIOLED_I175_P: DS4.A(P) R75.2(N2)
UNNAMED_8_DIOLED_I315_P: DS5.A(P) R155.1
UNNAMED_8_RES_I3_N2: R110.2(N2) R115.1 Y1.1
UNNAMED_8_RES_I27_N1: R109.1 Y1.3
UNNAMED_8_RES_I113_N2: Q3.2 R37.2(N2)
UNNAMED_9_AD1937_I165_ABCLK: R58.2(N2) U7.21 U7.28
UNNAMED_9_AD1937_I165_ADC2LN: R43.1 U7.58
UNNAMED_9_AD1937_I165_ADC2LP: R60.1 U7.57
UNNAMED_9_AD1937_I165_ADC2RN: R61.1 U7.60
UNNAMED_9_AD1937_I165_ADC2RP: R124.1 U7.59
UNNAMED_9_AD1937_I165_ALRCLK: R59.2(N2) U7.22 U7.29
UNNAMED_9_AD1937_I165_ASDATA1: R105.1 U7.27
UNNAMED_9_AD1937_I165_DSDATA1: R104.2(N2) U7.20
UNNAMED_9_AD1937_I165_FILTR: C47.P C127.2(N2) U7.47
UNNAMED_9_AD1937_I165_LF: C60.2(N2) C63.2(N2) U7.61
UNNAMED_9_AD1937_I165_SCL: R132.1 U7.34
UNNAMED_9_AD1937_I165_SDA: R138.1 U7.31
UNNAMED_9_CAP_I223_N1: C63.1 R117.2(N2)
UNNAMED_10_ADG774_I1_D1: R92.2(N2) U8.4
UNNAMED_10_ADG774_I1_D2: R111.2(N2) U8.7
UNNAMED_10_ADG774_I1_D3: R113.2(N2) U8.9
UNNAMED_10_ADG774_I1_D4: R100.2(N2) U8.12
UNNAMED_10_ADG774_I1_ENN: R82.1 R83.1 U8.15
UNNAMED_10_ADG774_I1_IN: JP47.2(N2) R80.1 U8.1
UNNAMED_10_ADG774_I1_S1A: R86.2(N2) U8.2
UNNAMED_10_ADG774_I1_S1B: R90.1 U8.3
UNNAMED_10_ADG774_I1_S2A: R97.2(N2) U8.5
UNNAMED_10_ADG774_I1_S2B: R102.1 U8.6
UNNAMED_10_ADG774_I1_S3A: R106.2(N2) U8.11
UNNAMED_10_ADG774_I1_S3B: R108.1 U8.10
UNNAMED_10_ADG774_I1_S4A: R89.2(N2) U8.14
UNNAMED_10_ADG774_I1_VDD: C37.2(N2) C38.2(N2) E9.1 R83.2(N2) U8.16(VDD)
UNNAMED_10_ADMAX16823_I78_CS1: DS6.3(C3) R153.2(N2) TP20.1(N1) U10.15
UNNAMED_10_ADMAX16823_I78_CS2: DS6.2 R152.2(N2) TP22.1(N1) U10.14
UNNAMED_10_ADMAX16823_I78_CS3: DS6.1 R151.2(N2) TP23.1(N1) U10.13
UNNAMED_10_ADMAX16823_I78_LGC: C15.2(N2) U10.10
UNNAMED_10_ADMAX16823_I78_OUT1: DS6.4 U10.2
UNNAMED_10_ADMAX16823_I78_OUT2: DS6.5 U10.1
UNNAMED_10_ADMAX16823_I78_OUT3: DS6.6 U10.16
UNNAMED_10_ADMAX16823_I78_REG: C87.2(N2) U10.11(REG)
UNNAMED_10_FERRITE_I73_N1: C85.2(N2) E11.1 TP19.1(N1) U10.7 U10.8 U10.9
UNNAMED_10_RES_I13_N2: R108.2(N2) R156.2(N2) U10.5
UNNAMED_10_RES_I16_N2: R102.2(N2) R149.2(N2) U10.4
UNNAMED_10_RES_I19_N2: R90.2(N2) R150.2(N2) U10.3
UNNAMED_11_CAP_I16_N2: C75.2(N2) C77.2(N2) C89.2(N2) C96.2(N2) E12.1 U11.2 U11.5(VDD) U12.5(VDD) U13.2 U13.5(VDD) U14.5(VDD)
UNNAMED_11_CN2P_I108_N1: JP3.1 R74.1
UNNAMED_11_CN2P_I108_N2: JP3.2(N2) R246.2(N2) U21.7(WP)
UNNAMED_11_FERRITE_I94_N1: E16.1 U21.8
UNNAMED_11_IC24XX512_I83_A0: R15.1 R16.2(N2) U21.1
UNNAMED_11_IC24XX512_I83_A1: R19.1 R24.2(N2) U21.2
UNNAMED_11_IC24XX512_I83_A2: R26.1 R30.2(N2) U21.3
UNNAMED_11_IC24XX512_I83_SCL: R25.1 U21.6
UNNAMED_11_IC24XX512_I83_SDA: R29.1 U21.5
UNNAMED_11_ICT3902_I102_CLK: R157.1 U11.4 U12.4 U13.4 U14.4
UNNAMED_11_ICT3902_I102_DATA: R130.1 U11.1
UNNAMED_11_ICT3902_I103_DATA: R131.1 U12.1
UNNAMED_11_ICT3902_I104_DATA: R158.1 U13.1
UNNAMED_11_ICT3902_I105_DATA: R141.1 U14.1
UNNAMED_12_ADLT3502_I229_BD: C20.2(N2) C21.2(N2) C118.2(N2) E18.1 L7.2(N2) R160.1 U16.2
UNNAMED_12_ADLT3502_I229_BOOST: C113.1 U16.7
UNNAMED_12_ADLT3502_I229_DA: D1.A(P) U16.6
UNNAMED_12_ADLT3502_I229_SHDNN: C105.2(N2) R162.1 U16.4
UNNAMED_12_ADLT3502_I229_SW: C113.2(N2) D1.C L7.1 U16.8
UNNAMED_12_ADLTC4368V2_I398_GATE: Q1.2 Q1.4 R13.2(N2) U3.10
UNNAMED_12_ADLTC4368V2_I398_SHDNN: R27.1 U3.6
UNNAMED_12_ADP2360_I325_FB: C115.2(N2) R164.2(N2) R167.1 U19.4
UNNAMED_12_ADP2360_I325_ITH: R163.2(N2) U19.3
UNNAMED_12_ADP2360_I325_SS: C25.2(N2) U19.5
UNNAMED_12_ADP2360_I325_SW: L12.1 U19.7
UNNAMED_12_CAP_I278_N2: C7.2(N2) D3.C L13.1 P1.1 P2.1 TP1.1(N1)
UNNAMED_12_CAP_I279_N2: C8.2(N2) D7.A(P) L13.2(N2) Q1.7 Q1.8 R10.2(N2) R17.2(N2) U3.1
UNNAMED_12_CAP_I301_N2: C28.2(N2) C115.1 C121.2(N2) E3.1 L12.2(N2) R167.2(N2)
UNNAMED_12_CAP_I303_N2: C6.2(N2) R28.1 U3.4
UNNAMED_12_CAP_I350_N2: C3.2(N2) R13.1
UNNAMED_12_DIOLED_I200_P: DS3.A(P) R32.1
UNNAMED_12_DIOLED_I290_P: DS8.A(P) R33.1
UNNAMED_12_DIOLED_I334_P: DS2.A(P) R10.1
UNNAMED_12_DIOLED_I356_P: DS7.A(P) R36.1
UNNAMED_12_RES_I210_N1: R20.1 R23.2(N2) U3.3
UNNAMED_12_RES_I210_N2: R17.1 R20.2(N2) U3.2
UNNAMED_12_TRANNMOSFETDUAL_I282_S: Q1.1 Q1.3(S)
UNNAMED_13_ADA48412_I26_: C157.1 R204.1 R205.2(N2) U18.6
UNNAMED_13_ADA48412_I26_OUT: C157.2(N2) R200.1 R204.2(N2) R214.2(N2) U18.7
UNNAMED_13_ADA48412_I42_: R201.1 R214.1 U18.2
UNNAMED_13_ADA48412_I42_OUT: R198.1 R201.2(N2) U18.1
UNNAMED_13_ADA48412_I53_: R202.1 R213.1 U17.6
UNNAMED_13_ADA48412_I53_OUT: R197.1 R202.2(N2) U17.7
UNNAMED_13_ADA48412_I115_: C161.2(N2) R221.2(N2) U5.3
UNNAMED_13_ADA48412_I115__1: C155.1 R219.2(N2) U5.2
UNNAMED_13_ADA48412_I115_OUT: C155.2(N2) R217.2(N2) R236.1 U5.1
UNNAMED_13_ADA48412_I139_: C165.2(N2) R224.2(N2) U5.5
UNNAMED_13_ADA48412_I139__1: C164.1 R222.2(N2) U5.6
UNNAMED_13_ADA48412_I139_OUT: C164.2(N2) R218.2(N2) R237.1 U5.7
UNNAMED_13_ADA48412_I160_: C158.1 R207.2(N2) R208.1 U17.2
UNNAMED_13_ADA48412_I160_OUT: C158.2(N2) R196.1 R208.2(N2) R213.2(N2) U17.1
UNNAMED_13_CAP_I35_N2: C91.1 C93.2(N2) P29.3 R145.2(N2) TP5.1(N1)
UNNAMED_13_CAP_I36_N2: C91.2(N2) R129.1 S1.2
UNNAMED_13_CAP_I69_N1: C90.1 C92.2(N2) P29.2 R144.2(N2) TP6.1(N1)
UNNAMED_13_CAP_I69_N2: C90.2(N2) R123.1 S1.5
UNNAMED_13_CAP_I87_N1: C143.1 R197.2(N2)
UNNAMED_13_CAP_I88_N1: C142.1 R196.2(N2)
UNNAMED_13_CAP_I89_N1: C147.1 R200.2(N2)
UNNAMED_13_CAP_I90_N1: C144.1 R198.2(N2)
UNNAMED_13_CAP_I126_N2: C106.2(N2) R194.2(N2) R217.1 R219.1
UNNAMED_13_CAP_I128_N1: C148.1 C166.2(N2) R192.2(N2) R221.1
UNNAMED_13_CAP_I144_N2: C149.2(N2) R212.2(N2) R218.1 R222.1
UNNAMED_13_CAP_I147_N1: C150.1 C167.2(N2) R211.2(N2) R224.1
UNNAMED_13_CAP_I164_N1: C167.1 R216.2(N2)
UNNAMED_13_CAP_I165_N1: C166.1 R215.2(N2)
UNNAMED_13_CAPP_I155_N1: C19.P R236.2(N2)
UNNAMED_13_CAPP_I155_N2: C19.N(N2) P28.2 R128.2(N2)
UNNAMED_13_CAPP_I158_N1: C130.P R237.2(N2)
UNNAMED_13_CAPP_I158_N2: C130.N(N2) P28.3 R250.2(N2)
UNNAMED_13_RES_I31_N2: R129.2(N2) R205.1 S1.3
UNNAMED_13_RES_I67_N1: R123.2(N2) R207.1 S1.6(NO2)
UNNAMED_14_7404V6_I71_Y: R239.1 U28.4
UNNAMED_14_ADMAX22503E_I16_A: D8.6 R188.2(N2) T2.8 U20.12
UNNAMED_14_ADMAX22503E_I16_B: D8.3 R188.1 T2.5 U20.11
UNNAMED_14_ADMAX22503E_I16_Y: D9.6 R206.1 U20.9
UNNAMED_14_ADMAX22503E_I16_Z: D9.3 R209.1 T3.8 U20.10(Z)
UNNAMED_14_CAP_I5_N1: C160.1 T3.5
UNNAMED_14_CAP_I5_N2: C160.2(N2) R210.1
UNNAMED_14_CAP_I27_N2: C153.2(N2) P3.2 P3.3 P3.4(N4) T2.1
UNNAMED_14_CN2P_I102_N1: JP2.1 R180.1
UNNAMED_14_CN4PV4_I1_N1: P5.1 T3.4
UNNAMED_14_CN4PV4_I1_N2: C168.2(N2) P5.2 P5.3 P5.4(N4) T3.1
UNNAMED_14_CN4PV4_I26_N1: P3.1 T2.4
UNNAMED_14_DIOLED_I76_P: DS11.A(P) R239.2(N2)
UNNAMED_14_RES_I37_N2: R206.2(N2) R209.2(N2) R210.2(N2)
USB_RESET: C2.2(N2) R5.2(N2) R225.1 U1.2
USBI_SCL: P32.87 R64.1 R70.1 R234.1 U27.4
USBI_SDA: P32.83 R55.1 R76.2(N2) R233.1 U26.4
VOUT2_3V3: C43.2(N2) C55.2(N2) C57.2(N2) C59.2(N2) E2.2(N2) TP15.1(N1) U9.31 U9.45
WKUP_24V: D7.C JP4.1 Q2.4
YLED_ANODE: P22.9 R46.1
YLED_CATHODE: P22.10 Q2.1

Pads without a net: P30 2; P32 4 8 12 16 20 24 28 31 32 35 36 40 44 48 51 52 56 60 64 68 72 76 80 84 93 95 96 97 98 99 100; S1 1 4; T2 2 3; T3 2 3; U3 7; U6 22 27 60 65; U7 3 6 7 8 9 10 11 12 13 15 18 19 26 40 41 42 43 49 50 63 64; U8 13; U10 6; U20 1 8; U28 1

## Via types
v1: diameter 0.508, hole 0.254, TOP to BOTTOM, 1141 vias

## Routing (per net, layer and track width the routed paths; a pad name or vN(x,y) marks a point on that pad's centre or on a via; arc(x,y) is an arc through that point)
DGND: length 1091.6
  TOP w0.203: U6.19 34.88,36.81 34.19,36.81 v1(33.91,37.08) 33.71,36.88 U6.17 33.71,35.64 34.04,35.31 34.04,35.06 C129.1 ; U6.25 32.39,39.78 v1(32.16,39.55)
  TOP w0.254: U9.26 114.14,32.93 114.3,32.77 ; v1(50.86,37.91) 50.85,37.93 U7.44 48.56,37.93 ; v1(109.09,33.4) 109.07,33.42 U9.10 ; U6.37 34.9,45.98 v1(34.91,45.97) U6.36 ; v1(111.7,36.96) 111.7,37.42 112.19,37.92 U9.38 ; U9.1 104.85,37.92 104.39,37.46 v1(104.39,36.96) ; U3.5 49.86,56.98 v1(50.16,57.28) ; U3.5 49.07,56.44 ; U3.5 48.21,56.98 ; U6.72 25.01,36.18 24.07,35.24 24.07,34.54 23.27,33.74 C76.1 ; U7.46 v1(50.93,36.93) ; C43.1 118.06,33.66 117.6,33.66 116.33,34.92 U9.30 ; U9.20 110.69,33.29 v1(110.81,33.4) ; U6.6 28.21,34.93 C62.1 ; C55.1 118.03,37.23 117.71,37.23 116.4,35.92 U9.32 112.47,35.92 112.33,36.07 v1(111.7,36.07) ; U6.55 25.01,45.97 v1(25.02,45.98) U6.54 ; C61.1 32.21,34.86 U6.14 ; C56.1 24.77,35.18 25.03,35.43 25.5,35.43 25.71,35.64 U6.1 ; U9.44 109.19,37.06 v1(109.09,36.96) ; v1(109.09,36.07) 108.74,36.42 U9.4
  TOP w0.305: C65.1 v1(148.84,23.77) ; C65.1 v1(148.84,22.2) ; C65.1 v1(149.59,22.99) ; C24.1 v1(157.21,48.01) ; C24.1 v1(156.46,48.79) ; C24.1 v1(156.46,47.22) ; C39.2 v1(156.46,41.17) ; C39.2 v1(156.46,39.6) ; C39.2 v1(157.21,40.39) ; v1(116.46,44.64) R72.1 ; v1(148.84,31.27) C80.2 v1(148.84,29.69) ; v1(115.38,44.64) R73.1
  TOP w0.406: C171.2 v1(128.4,16.39) ; U27.3 v1(132.37,15.62) ; U26.3 v1(137.2,15.62) ; C170.2 v1(133.22,16.39)
  TOP w0.508: 14.91,19.3 P15.4 ; P15.4 14.91,17.53 ; P15.4 16.69,17.53 ; P15.4 16.69,19.3 ; C2.1 112.15,62.64 ; C2.1 111.57,62.1 ; C2.1 110.98,62.64 ; 64.71,37.28 TP12.1 ; TP12.1 66.48,39.05 ; TP12.1 64.71,39.05 ; TP12.1 66.48,37.28 ; 94.32,15.24 C178.1 ; C178.1 95.05,14.49 ; C178.1 95.05,15.99 ; R31.1 173.65,59.82 ; R31.1 v1(171.89,59.82) ; R31.1 172.87,60.95 ; R31.1 172.87,58.69 ; C35.2 v1(134.73,28.82) ; 126.53,17.41 C84.1 ; C84.1 v1(126.53,19.11) ; C84.1 127.25,18.16 ; 109.92,12.18 C89.1 ; C89.1 109.38,12.76 ; C89.1 v1(109.92,13.55) ; C77.1 v1(100.34,19.08) ; C77.1 100.34,17.7 ; C77.1 99.79,18.29 ; 8.64,16.35 C15.1 8.06,16.9 ; 9.53,41.07 C38.1 ; C38.1 9.53,42.24 ; C38.1 8.99,41.66 ; P1.3 21.5,65.8 ; P1.3 21.5,63.49 ; P1.3 19.19,65.8 ; P1.3 19.19,63.49 ; C176.1 80.91,15.44 ; C176.1 80.91,14.27 ; C176.1 80.37,14.86 ; P4.2 85.25,12.23 ; P4.2 83.66,10.63 ; P4.2 85.25,10.63 ; P4.2 83.66,12.23 ; DS9.C v1(97.07,27.43) ; DS9.C 98.01,26.8 ; DS9.C 98.01,28.07 ; 119.74,60.97 U2.1 ; U2.1 120.63,60.17 ; U2.1 121.52,60.97 ; U2.1 120.63,61.77 ; v1(112.6,15.45) 113.22,15.45 ; v1(112.6,15.45) 111.97,15.45 ; v1(112.6,15.45) 112.6,15.97 ; 14.91,22.61 P15.8 14.91,24.38 ; C52.1 v1(21.84,33.53) 23.03,33.53 C76.1 ; C52.1 21.26,34.42 ; C52.1 22.43,34.42 ; R112.1 v1(171.89,57.4) ; R112.1 172.87,56.27 ; R112.1 172.87,58.53 ; R112.1 173.65,57.4 ; v1(7.11,8.95) R152.1 ; R152.1 6.16,9.97 ; R152.1 7.11,10.75 ; R152.1 8.07,9.97 ; 117.63,59.89 C5.1 117.09,59.31 ; R96.1 173.65,35.94 ; R96.1 v1(171.89,35.94) ; R96.1 172.87,37.07 ; SW1.4 108.01,64.11 ; SW1.4 107.31,63.36 ; SW1.4 106.61,64.11 ; 23.89,68.8 P1.2 ; P1.2 23.89,66.49 ; P1.2 26.2,68.8 ; P1.2 26.2,66.49 ; 158.15,4.91 P30.10 ; P30.10 159.83,4.91 ; P30.10 159.83,6.59 ; P30.10 158.15,6.59 ; DS5.C 146.81,11.68 ; DS5.C 147.83,10.92 ; DS5.C v1(145.59,10.92) ; DS5.C 146.81,10.16 ; 14.91,34.54 P15.16 ; R42.1 144.4,37.65 ; R42.1 145.02,37.08 ; R42.1 143.78,37.08 ; C85.1 7.24,18.34 v1(7.24,17.66) ; 113.1,62.13 U1.3 ; U1.3 112.25,62.69 ; U1.3 113.95,62.69 ; 4.87,10.21 R151.1 ; R151.1 4.87,11.76 ; R151.1 4.89,10.97 v1(4.89,9.97) ; R151.1 5.83,10.99 ; R151.1 3.92,10.99 ; 36.73,12.95 R250.1 ; R250.1 37.3,13.58 ; R250.1 37.3,12.33 ; 23.31,12.33 R145.1 22.74,12.95 ; C92.1 R144.1 v1(35.31,12.19) ; C92.1 35.31,14.62 ; C92.1 35.85,14.03 ; P15.2 16.69,14.99 ; P15.2 14.91,16.76 ; P15.2 16.69,16.76 ; C179.1 100.19,15.82 ; C179.1 100.73,15.24 ; C179.1 100.19,14.66 ; R110.1 43.93,28.44 ; R110.1 43.31,29.01 ; R110.1 42.68,28.44 ; 49.47,49.02 R143.1 ; R143.1 50.05,48.4 ; R143.1 50.05,49.64 ; R128.1 49.37,12.89 v1(50.04,12.89) ; R128.1 49.3,12.33 ; R128.1 49.3,13.58 ; R128.1 49.88,12.95 ; 50.57,47.7 C66.1 50.57,46.53 ; 45.47,51.69 P8.9 ; P8.9 47.24,51.69 ; P8.9 47.24,53.46 ; P8.9 45.47,53.46 ; C56.1 v1(24.77,33.4) ; C73.1 38.14,46.22 ; C73.1 38.22,45.55 C36.1 v1(38.22,47.49) ; C73.1 38.86,45.47 ; 37.64,28.31 C67.2 ; C67.2 38.81,28.31 ; C67.2 38.23,28.86 ; P2.2 40,65.06 ; P2.2 40,63.11 ; P2.2 38.05,65.06 ; P2.2 38.05,63.11 ; 51.19,31.67 C109.1 50.64,32.26 ; 27.95,5.5 P29.1 30.67,5.5 ; C96.1 107.96,3.67 ; C96.1 v1(107.21,3.08) ; C96.1 107.96,2.5 ; C59.1 125.09,36.72 ; C59.1 125.09,34.15 ; C59.1 125.89,35.43 ; C59.1 124.29,35.43 ; 116.28,65.96 C131.1 115.73,66.55 ; 14.91,21.84 P15.6 ; P15.6 14.91,20.07 ; P15.6 16.69,20.07 ; 48.65,54.57 DS8.C ; DS8.C 50.36,54.57 ; DS8.C 49.5,53.71 ; DS8.C 49.5,55.42 ; R80.2 4.41,42.23 ; R80.2 3.84,41.6 ; R80.2 4.41,40.98 ; 16.69,30.23 P15.14 14.91,30.23 ; 47.94,38.97 C107.1 47.36,38.43 ; C49.1 v1(134.73,42.04) ; R93.1 v1(156.6,15.62) ; R93.1 155.82,16.24 ; R93.1 155.82,15 ; R135.1 v1(110.3,22.99) ; 16.69,29.46 P15.12 14.91,29.46 ; SW1.1 103.92,64.11 ; SW1.1 103.22,63.36 ; SW1.1 102.52,64.11 ; 11.31,7.62 TP21.1 ; TP21.1 13.08,7.62 ; TP21.1 13.08,5.84 ; TP21.1 11.31,5.84 ; U28.3 v1(143.32,15.61) ; R153.1 10.48,6.61 ; R153.1 9.52,7.38 ; R153.1 8.57,6.61 ; R153.1 v1(9.52,5.59) ; C46.1 110.73,44.87 ; C46.1 109.23,44.87 ; C46.1 v1(109.98,45.85) ; R82.2 v1(13.45,38.04) ; C74.1 14.1,58.81 ; C74.1 14.9,57.53 ; C74.1 14.1,56.25 ; C74.1 13.3,57.53 ; v1(46.36,61.15) C3.1 ; C11.1 v1(34.54,53.4) ; DS10.C 97.99,25.77 v1(97.99,24.64) ; DS10.C 97.27,25.78 ; DS10.C 98.01,25.15 ; DS10.C 98.01,26.42 ; 84.67,17.14 C177.1 85.39,17.89 ; Y1.2 42.57,29.77 ; Y1.2 41.72,28.82 ; Y1.2 41.72,30.73 ; U15.4 v1(121.69,6.86) ; DS4.C v1(40.8,52.83) ; DS4.C 41.67,51.82 ; DS4.C 40.8,51.02 ; DS4.C 39.92,51.82 ; C94.2 v1(123.46,12.19) ; C94.2 124.21,12.78 ; C94.2 124.21,11.61 ; C17.1 v1(25.78,53.4) ; 64.37,42.42 C162.1 63.83,41.83 ; 51.19,31.32 C112.1 50.64,30.73 ; 157.81,41.39 L6.1 ; L6.1 v1(158.75,40.47) ; L6.1 159.69,41.39 ; v1(63.75,38.73) 63.7,38.68 C110.1 ; 49.07,29.02 C83.1 ; C83.1 49.97,30.07 ; C83.1 49.97,27.96 ; DS2.C 45.47,68.45 v1(45.66,68.26) ; DS2.C 44.39,67.44 ; DS2.C 43.62,68.45 ; 119.92,17.7 C75.1 ; C75.1 119.38,18.29 ; C75.1 v1(119.92,19.08) ; 120.78,31.63 TP14.1 122.55,31.63 ; R23.1 v1(44.84,58.98) ; 16.69,52.32 P15.30 14.91,52.32 ; DS11.C 141.31,19.94 ; DS11.C 140.43,19.14 ; DS11.C 140.43,20.74 ; DS11.C v1(139.19,19.94) ; TP9.1 49.65,25.66 ; TP9.1 47.88,27.43 ; TP9.1 49.65,27.43 ; 173.25,51.46 P10.8 P10.6 ; C57.1 v1(120.38,35.43) ; v1(38.23,33.02) C42.1 37.22,33.66 C78.1 ; P6.1 102.78,12.48 ; P6.1 102.78,10.38 ; P6.1 100.67,10.38 ; P6.1 100.67,12.48 ; 104.16,63.47 SW1.5 ; SW1.5 105.27,64 ; SW1.5 105.27,62.94 ; SW1.5 106.37,63.47 ; v1(116.08,65.6) 116.9,65.6 C1.1 ; 117.09,58.23 C163.1 ; C163.1 117.63,57.64 ; C163.1 117.79,58.07 v1(117.79,57.4) ; v1(22.35,14.03) C93.1 ; R85.2 v1(38.44,39.37) ; C172.1 v1(139.19,16.15) ; v1(6.86,31.5) 6.62,31.25 U8.8 ; 170.42,42.04 P10.1 170.42,44.15 ; 134.75,6.86 v1(136.3,6.86) ; 9.65,16.35 C87.1 10.24,16.9 ; v1(118.87,33.4) C43.1 ; R28.2 v1(47.68,55.97) ; C16.1 v1(26.92,53.4) ; 44.66,5.5 P28.1 41.94,5.5 ; R21.1 v1(115.76,22.99) ; v1(118.87,37.46) C55.1 ; 16.69,45.47 P15.26 14.91,45.47 ; C61.1 v1(32.01,34.04) ; v1(102.6,21.22) 103.22,21.22 ; v1(102.6,21.22) 102.6,21.74 ; v1(102.6,21.22) 101.97,21.22 ; 43.81,52.58 44.7,53.46 ; 43.81,52.58 42.93,53.46 ; 43.81,52.58 44.7,51.69 ; 43.81,52.58 42.93,51.69 ; C100.1 119.25,3.08 ; C100.1 118.53,2.33 ; C100.1 v1(118.53,4.03) ; 129.74,16.39 C171.2 129.16,15.84 ; C23.2 22.61,48.18 C69.1 ; C10.1 v1(35.69,53.4) ; C71.1 105.74,23.88 ; C71.1 v1(105.16,23.24) ; C71.1 104.57,23.88 ; C127.1 48.46,35.43 ; C127.1 47.88,34.88 ; C127.1 47.29,35.43 ; 14.91,54.86 P15.32 ; P15.32 16.69,54.86 ; P15.32 16.69,53.09 ; P15.32 14.91,53.09 ; C12.1 v1(32,53.4) ; 14.91,25.15 P15.10 ; C169.2 v1(146.18,16.15) ; C9.1 v1(36.83,53.4) ; C51.2 v1(98.17,36.2) ; C62.1 v1(27.95,34.04) ; R244.1 v1(129.04,9.4) ; C6.1 v1(44.84,55.97) ; C26.1 v1(36.19,46.74) ; DS7.C 86.93,49.91 ; DS7.C 86.08,49.06 ; DS7.C 87.78,49.06 ; DS7.C 86.93,48.21 ; R176.2 v1(33.15,51.05) ; C37.1 8.57,44.49 ; C37.1 8.57,42.38 ; C37.1 7.67,43.43 ; v1(21.59,46.48) C27.1 ; C41.2 v1(100.1,37.46) ; 161.39,25.26 C72.2 161.93,24.67 ; C50.2 v1(134.73,46.23) ; U25.3 v1(150.3,15.61) ; C4.2 v1(135.9,11.91) ; 14.91,44.7 P15.24 16.69,44.7 ; C64.2 v1(98.81,30.49) ; C18.1 v1(24.64,53.4) ; C8.1 v1(38.29,53.91) ; R246.1 v1(142.87,10.22) ; C34.1 v1(134.73,24.64)
  TOP w0.635: P10.14 176.15,57.13 R112.2 R31.2 175.87,61.62 TP2.1 ; P10.13 176.15,36.22 R96.2
  L2_GND w0.508: 11.31,5.84 TP21.1 ; TP21.1 13.08,5.84 ; TP21.1 11.31,7.62 ; TP21.1 13.08,7.62 ; TP14.1 122.55,31.63 ; TP14.1 120.78,33.4 ; TP14.1 120.78,31.63 ; 14.91,34.54 P15.16 ; P15.16 16.69,32.77 ; P15.16 14.91,32.77 ; P15.16 16.69,34.54 ; 27.95,5.5 P29.1 30.67,5.5 ; TP12.1 66.48,37.28 ; TP12.1 64.71,39.05 ; TP12.1 64.71,37.28 ; TP12.1 66.48,39.05 ; P15.10 16.69,26.92 ; P15.10 16.69,25.15 ; P15.10 14.91,25.15 ; P15.10 14.91,26.92 ; 23.89,68.8 P1.2 ; P1.2 23.89,66.49 ; P1.2 26.2,68.8 ; P1.2 26.2,66.49 ; 14.91,40.39 P15.22 ; P15.22 16.69,40.39 ; P15.22 14.91,42.16 ; P15.22 16.69,42.16 ; P15.8 16.69,24.38 ; P15.8 16.69,22.61 ; P15.8 14.91,24.38 ; P15.8 14.91,22.61 ; 44.66,5.5 P28.1 41.94,5.5 ; P8.9 47.24,53.46 ; P8.9 45.47,51.69 ; P8.9 47.24,51.69 ; P8.9 45.47,53.46 ; 14.91,14.99 P15.2 ; P15.2 16.69,14.99 ; P15.2 14.91,16.76 ; P15.2 16.69,16.76 ; 14.91,21.84 P15.6 ; P15.6 16.69,20.07 ; P15.6 16.69,21.84 ; P15.6 14.91,20.07 ; P1.3 21.5,63.49 ; P1.3 19.19,63.49 ; P1.3 21.5,65.8 ; P1.3 19.19,65.8 ; P15.4 16.69,17.53 ; P15.4 16.69,19.3 ; P15.4 14.91,19.3 ; P15.4 14.91,17.53 ; 14.91,32 P15.14 ; P15.14 16.69,30.23 ; P15.14 14.91,30.23 ; P15.14 16.69,32 ; P6.1 102.52,10.63 ; P6.1 102.52,12.23 ; P6.1 100.93,10.63 ; P6.1 100.93,12.23 ; 170.67,42.3 P10.1 170.67,43.89 ; 14.91,29.46 P15.12 ; P15.12 14.91,27.69 ; P15.12 16.69,29.46 ; P15.12 16.69,27.69 ; 14.91,37.08 P15.18 ; P15.18 16.69,35.31 ; P15.18 14.91,35.31 ; 43.81,52.58 44.7,51.69 ; 43.81,52.58 42.93,51.69 ; 43.81,52.58 44.7,53.46 ; 43.81,52.58 42.93,53.46 ; TP9.1 49.65,27.43 ; TP9.1 49.65,25.66 ; TP9.1 47.88,27.43 ; P15.28 16.69,49.78 ; P15.28 14.91,48.01 ; P15.28 14.91,49.78 ; P15.28 16.69,48.01 ; 14.91,37.85 P15.20 ; P15.20 14.91,39.62 ; P15.20 16.69,39.62 ; 38.05,63.11 P2.2 ; P2.2 38.05,65.06 ; P2.2 40,65.06 ; P2.2 40,63.11 ; P4.2 85.25,12.23 ; P4.2 83.66,12.23 ; P4.2 85.25,10.63 ; P4.2 83.66,10.63 ; 14.91,45.47 P15.26 ; P15.26 14.91,47.24 ; P15.26 16.69,47.24 ; P15.26 16.69,45.47 ; P30.10 159.83,4.91 ; P30.10 159.83,6.59 ; P30.10 158.15,6.59 ; P30.10 158.15,4.91 ; P15.24 16.69,44.7 ; P15.24 14.91,42.93 ; P15.24 16.69,42.93 ; P15.24 14.91,44.7 ; P15.30 16.69,52.32 ; P15.30 14.91,50.55 ; P15.30 16.69,50.55 ; P15.30 14.91,52.32 ; 14.91,54.86 P15.32 ; P15.32 16.69,54.86 ; P15.32 14.91,53.09 ; P15.32 16.69,53.09 ; 173.25,51.46 P10.8 P10.6
  L3_SIG w0.508: P6.1 102.52,12.23 ; P6.1 100.93,10.63 ; P6.1 100.93,12.23 ; P6.1 102.52,10.63 ; 23.89,68.8 P1.2 ; P1.2 23.89,66.49 ; P1.2 26.2,66.49 ; P1.2 26.2,68.8 ; P15.20 15.8,39.92 ; P15.20 14.62,38.73 ; P15.20 15.8,37.55 ; 14.91,49.78 P15.28 16.69,49.78 ; 19.19,65.8 P1.3 ; P1.3 21.5,63.49 ; P1.3 21.5,65.8 ; P1.3 19.19,63.49 ; P15.22 15.8,42.46 ; P15.22 14.62,41.27 ; P15.22 15.8,40.09 ; 14.91,54.86 P15.32 14.91,53.09 ; 14.91,34.54 P15.16 ; P15.16 14.91,32.77 ; P15.16 16.69,32.77 ; P15.16 16.69,34.54 ; TP21.1 13.08,7.62 ; TP21.1 11.31,7.62 ; TP21.1 11.31,5.84 ; TP21.1 13.08,5.84 ; 14.91,42.93 P15.24 16.69,42.93 ; P15.2 16.69,16.76 ; P15.2 16.69,14.99 ; P15.2 14.91,16.76 ; P15.2 14.91,14.99 ; 30.67,5.5 P29.1 27.95,5.5 ; P15.30 16.69,50.55 ; P15.30 14.91,52.32 ; P15.30 16.69,52.32 ; P15.30 14.91,50.55 ; TP14.1 122.55,31.63 ; TP14.1 120.78,31.63 ; TP14.1 120.78,33.4 ; TP9.1 49.65,27.43 ; TP9.1 49.65,25.66 ; TP9.1 47.88,27.43 ; 14.91,17.53 P15.4 ; P15.4 14.91,19.3 ; P15.4 16.69,17.53 ; P15.4 16.69,19.3 ; 14.91,32 P15.14 16.69,32 ; TP12.1 66.48,39.05 ; TP12.1 66.48,37.28 ; TP12.1 64.71,37.28 ; TP12.1 64.71,39.05 ; 83.66,12.23 P4.2 ; P4.2 85.25,10.63 ; P4.2 83.66,10.63 ; P4.2 85.25,12.23 ; 170.67,43.89 P10.1 170.67,42.3 ; 16.69,20.07 P15.6 14.91,20.07 ; 14.91,37.08 P15.18 14.91,35.31 ; 41.94,5.5 P28.1 44.66,5.5 ; 38.05,63.11 P2.2 ; P2.2 40,65.06 ; P2.2 38.05,65.06 ; P2.2 40,63.11 ; 173.25,51.46 P10.8 P10.6 ; P30.10 159.83,4.91 ; P30.10 158.15,4.91 ; P30.10 158.15,6.59 ; P30.10 159.83,6.59 ; P15.26 14.45,46.35
  L5_GND w0.508: P6.1 102.52,12.23 ; P6.1 100.93,10.63 ; P6.1 102.52,10.63 ; P6.1 100.93,12.23 ; 14.91,20.07 P15.6 ; P15.6 14.91,21.84 ; P15.6 16.69,21.84 ; P15.6 16.69,20.07 ; 14.91,44.7 P15.24 ; P15.24 16.69,42.93 ; P15.24 16.69,44.7 ; P15.24 14.91,42.93 ; 14.91,30.23 P15.14 ; P15.14 14.91,32 ; P15.14 16.69,32 ; P15.14 16.69,30.23 ; P1.3 21.5,63.49 ; P1.3 19.19,63.49 ; P1.3 21.5,65.8 ; P1.3 19.19,65.8 ; P2.2 40,65.06 ; P2.2 40,63.11 ; P2.2 38.05,63.11 ; P2.2 38.05,65.06 ; P15.16 16.69,32.77 ; P15.16 14.91,34.54 ; P15.16 16.69,34.54 ; P15.16 14.91,32.77 ; 14.91,48.01 P15.28 ; P15.28 16.69,48.01 ; P15.28 14.91,49.78 ; P15.28 16.69,49.78 ; P15.18 16.69,35.31 ; P15.18 14.91,35.31 ; P15.18 14.91,37.08 ; TP12.1 66.48,39.05 ; TP12.1 64.71,39.05 ; TP12.1 64.71,37.28 ; TP12.1 66.48,37.28 ; 14.91,17.53 P15.4 ; P15.4 16.69,19.3 ; P15.4 16.69,17.53 ; P15.4 14.91,19.3 ; 45.47,53.46 P8.9 ; P8.9 47.24,53.46 ; P8.9 47.24,51.69 ; P8.9 45.47,51.69 ; 14.91,24.38 P15.8 ; P15.8 14.91,22.61 ; P15.8 16.69,22.61 ; P15.8 16.69,24.38 ; TP21.1 13.08,7.62 ; TP21.1 13.08,5.84 ; TP21.1 11.31,5.84 ; TP21.1 11.31,7.62 ; 14.91,40.39 P15.22 ; P15.22 16.69,40.39 ; P15.22 16.69,42.16 ; P15.22 14.91,42.16 ; 44.66,5.5 P28.1 41.94,5.5 ; 120.78,31.63 TP14.1 ; TP14.1 120.78,33.4 ; TP14.1 122.55,31.63 ; 30.67,5.5 P29.1 27.95,5.5 ; P4.2 85.25,12.23 ; P4.2 85.25,10.63 ; P4.2 83.66,12.23 ; P4.2 83.66,10.63 ; 14.91,39.62 P15.20 ; P15.20 14.91,37.85 ; P15.20 16.69,39.62 ; 14.91,45.47 P15.26 ; P15.26 14.91,47.24 ; P15.26 16.69,47.24 ; P15.26 16.69,45.47 ; 23.89,66.49 P1.2 ; P1.2 23.89,68.8 ; P1.2 26.2,66.49 ; P1.2 26.2,68.8 ; 14.91,14.99 P15.2 ; P15.2 16.69,14.99 ; P15.2 14.91,16.76 ; P15.2 16.69,16.76 ; 43.81,52.58 44.7,51.69 ; 43.81,52.58 42.93,51.69 ; 43.81,52.58 44.7,53.46 ; 43.81,52.58 42.93,53.46 ; P10.6 P10.8 173.25,51.46 ; P30.10 159.83,4.91 ; P30.10 158.15,4.91 ; P30.10 159.83,6.59 ; P30.10 158.15,6.59 ; P15.10 16.69,26.92 ; P15.10 16.69,25.15 ; P15.10 14.91,26.92 ; P15.10 14.91,25.15 ; 14.91,53.09 P15.32 ; P15.32 16.69,54.86 ; P15.32 14.91,54.86 ; P15.32 16.69,53.09 ; 14.91,52.32 P15.30 ; P15.30 14.91,50.55 ; P15.30 16.69,52.32 ; P15.30 16.69,50.55 ; 14.91,29.46 P15.12 ; P15.12 16.69,29.46 ; P15.12 14.91,27.69 ; P15.12 16.69,27.69 ; TP9.1 49.65,25.66 ; TP9.1 47.88,27.43 ; TP9.1 49.65,27.43 ; 170.67,42.3 P10.1 170.67,43.89
  BOTTOM w0.254: P32.13 10.03,23.18 ; U4.3 13.46,33.64 13.48,33.66 v1(14.23,33.66) ; U4.1 13.08,34.94 13.08,35.43 ; U4.1 12.33,34.94 ; U4.1 13.83,34.94 ; P32.9 10.1,21.91
  BOTTOM w0.305: P32.17 v1(7.47,24.45) ; R150.1 3.61,38.42 P32.62 v1(7.47,38.42) P32.61 ; P32.33 v1(7.47,29.53) ; P32.49 v1(7.47,34.61) P32.50 3.87,34.61 ; P32.14 v1(3.87,23.18) ; 55.82,61.89 56.61,61.89 C105.1 R184.1 57.79,61.23 v1(58,61.02) ; P32.25 v1(7.47,26.99) ; P32.37 v1(7.47,30.8) P32.38 3.87,30.8 ; P32.70 v1(6.38,40.96) ; P32.5 v1(7.47,20.64) ; P32.57 v1(7.47,37.15) P32.58 4,37.15 ; P32.69 v1(7.47,40.96) ; P32.22 v1(3.87,25.72) ; R149.1 3.48,33.34 P32.46 v1(7.47,33.34) P32.45 ; P32.81 v1(7.47,44.77) ; P32.74 v1(6.38,42.23) ; 3.87,32.07 P32.42 v1(7.47,32.07) P32.41 ; P32.65 v1(7.47,39.69) P32.66 ; 3.87,35.88 P32.54 v1(7.47,35.88) P32.53 ; P32.73 v1(7.47,42.23) ; P32.10 v1(3.87,21.91) ; P32.34 v1(6.38,29.53) ; P32.1 7.18,19.37 ; P32.26 v1(6.38,26.99) ; 9.83,47.94 P32.91 v1(7.47,47.94) ; 9.85,47.31 P32.89 v1(7.47,47.31) ; C175.1 v1(13.39,36.2) ; P32.18 v1(3.87,24.45) ; P32.77 v1(7.47,43.5) ; P32.2 v1(3.87,19.37) ; P32.29 v1(7.47,28.26) ; P32.78 v1(6.38,43.5) ; P32.21 v1(7.47,25.72) ; P32.6 v1(3.87,20.64) ; P32.82 v1(6.38,44.77) ; P32.85 v1(7.47,46.04) ; P32.30 v1(6.38,28.26)
  BOTTOM w0.381: v1(70.48,16.45) 70.37,16.33 D8.4 ; D9.4 67.76,17.91 v1(68.52,17.91) ; D8.1 67.78,15.05 v1(68.52,15.05)
  BOTTOM w0.406: D9.1 70.38,19.2 ; D9.1 69.66,19.78 ; D9.1 68.98,19.2 ; P32.94 v1(3.87,48.58) ; v1(3.87,47.94) P32.92 ; P32.90 v1(3.87,47.31)
  BOTTOM w0.508: 162.43,53.76 D4.A ; D4.A 161.57,54.47 ; D4.A 163.3,54.47 ; D4.A 162.43,55.18 ; v1(88.07,60.23) 87.53,59.69 R164.1 ; 16.69,14.99 P15.2 14.91,14.99 ; P4.2 85.25,10.63 ; P4.2 83.66,10.63 ; P4.2 83.66,12.23 ; P4.2 85.25,12.23 ; 85.03,66.93 C101.1 ; C101.1 86.08,64.9 ; C101.1 83.97,64.9 ; C101.1 85.03,63.64 ; P1.3 21.5,63.49 ; P1.3 19.19,65.8 ; P1.3 21.5,65.8 ; P1.3 19.19,63.49 ; C22.1 109.86,32.08 ; C22.1 109.32,31.5 ; C22.1 109.86,30.91 ; 110.69,33.22 C173.1 110.14,32.64 ; 36.53,25.26 C135.1 ; C135.1 35.98,25.84 ; C135.1 36.53,26.43 ; C136.1 29.58,26.43 ; C136.1 30.12,25.84 ; C136.1 29.58,25.26 ; 48.44,20.91 C165.1 ; C165.1 49.61,20.91 ; C165.1 49.02,20.36 ; R16.1 134.99,11.29 ; R16.1 135.57,10.67 ; R16.1 134.99,10.05 ; U20.6 61.7,18.98 ; U20.6 60.53,19.55 ; U20.6 59.36,18.98 ; 33.83,12.51 C138.1 ; C138.1 35,12.51 ; C138.1 34.42,11.96 ; U20.7 60.53,20.82 ; U20.7 61.7,20.25 ; U20.7 60.53,19.68 ; U20.7 59.36,20.25 ; 158.15,4.91 P30.10 ; P30.10 158.15,6.59 ; P30.10 159.83,6.59 ; P30.10 159.83,4.91 ; 176.15,63.12 TP2.1 176.15,61.34 ; C40.1 108.08,34.41 v1(108.2,34.29) ; C40.1 107.38,34.96 ; C40.1 106.79,34.41 ; C14.1 113.91,46.61 ; C14.1 112.65,45.55 ; C14.1 112.65,47.66 ; C14.1 111.39,46.61 ; C123.1 101.42,43.49 ; C123.1 98.86,43.49 ; C123.1 100.14,42.69 ; C123.1 100.14,44.29 ; 120.39,8.78 R146.1 ; R146.1 120.39,10.02 ; R146.1 120.96,9.4 ; v1(33.46,18.1) 33.46,17.32 C145.1 ; 14.91,50.55 P15.30 14.91,52.32 ; R168.2 160.27,57.1 ; R168.2 160.27,55.55 ; R168.2 161.23,56.32 ; R168.2 159.32,56.32 ; 47.57,19.82 C150.2 46.99,19.27 ; 11.55,18.08 C151.2 12.1,18.67 ; R133.1 120.39,8.75 ; R133.1 120.39,7.51 ; R133.1 120.96,8.13 ; 14.48,48.89 P15.28 14.91,49.78 ; v1(87.69,60.83) 86.99,60.83 R163.1 ; 41.94,5.5 P28.1 44.66,5.5 ; 33.47,16.73 C145.1 ; C145.1 32.93,17.32 ; C145.1 33.47,17.9 ; TP12.1 66.48,39.05 ; TP12.1 66.48,37.28 ; TP12.1 64.71,39.05 ; TP12.1 64.71,37.28 ; C88.1 37.71,39.11 37.97,39.37 v1(38.44,39.37) ; v1(32.16,42.21) 32.72,42.21 R179.1 ; R30.1 135.57,8.13 ; R30.1 134.99,8.75 ; R30.1 134.99,7.51 ; C48.1 130.52,44.88 ; C48.1 129.79,44.13 ; C48.1 130.52,43.38 ; 173.25,51.46 P10.8 P10.6 ; R149.1 3.42,33.9 ; R149.1 3.42,32.65 ; R149.1 3.99,33.27 ; 40,65.06 P2.2 38.05,65.06 ; P15.4 14.35,18.41 ; C13.1 109.94,38.85 ; C13.1 109.22,38.1 ; C13.1 109.94,37.35 ; P1.2 26.2,66.49 ; P1.2 23.89,68.8 ; P1.2 23.89,66.49 ; P1.2 26.2,68.8 ; 134.99,8.78 R24.1 ; R24.1 134.99,10.02 ; R24.1 135.57,9.4 ; P15.32 16.69,53.09 ; P15.32 14.91,53.09 ; P15.32 14.91,54.86 ; P15.32 16.69,54.86 ; 31.47,18.34 C82.1 ; C82.1 31.47,20.65 ; C82.1 30.65,19.49 ; C82.1 32.3,19.49 ; R147.1 120.96,10.67 ; R147.1 120.39,10.05 ; R147.1 120.39,11.29 ; 49.65,27.43 TP9.1 47.88,27.43 ; C116.2 109.22,54.51 ; C116.2 109.8,53.97 ; C116.2 108.64,53.97 ; 46.41,26.47 C149.1 ; C149.1 47.58,26.47 ; C149.1 47,27.02 ; 14.91,21.84 P15.6 ; 56.26,21.35 U5.4 ; U5.4 54.92,21.91 ; U5.4 57.61,21.91 ; 57.71,21.67 C161.1 ; C161.1 58.29,21.12 ; C161.1 R215.1 ; 44.7,53.46 43.81,52.58 42.93,53.46 ; 30.53,13.65 C137.1 ; C137.1 31.12,13.1 ; C137.1 31.7,13.65 ; 12.45,32.88 R156.1 11.88,32.26 ; 59.36,15.17 U20.3 61.7,15.17 ; 100.67,12.48 P6.1 ; P6.1 102.78,12.48 ; P6.1 102.78,10.38 ; P6.1 100.67,10.38 ; TP14.1 122.55,31.63 ; TP14.1 120.78,31.63 ; TP14.1 120.78,33.4 ; 165.12,55 R249.2 ; R249.2 164.35,56.13 ; R249.2 165.12,57.26 ; R249.2 165.9,56.13 ; U19.6 v1(80.45,60.87) ; C133.1 41.7,26.43 ; C133.1 42.25,25.84 ; C133.1 41.7,25.26 ; 11.31,5.84 TP21.1 ; TP21.1 13.08,7.62 ; TP21.1 11.31,7.62 ; TP21.1 13.08,5.84 ; 36.16,36.58 C125.1 36.71,35.99 ; 164.54,42.19 R248.1 ; R248.1 165.11,41.57 ; R248.1 165.11,42.82 ; 24.27,25.26 C140.1 ; C140.1 24.27,26.43 ; C140.1 23.73,25.84 ; 130.52,25.96 C33.1 ; C33.1 129.79,26.71 ; C33.1 130.52,27.46 ; v1(21.08,18.1) 21.08,17.32 C146.1 ; 63.01,21.67 C148.2 62.42,21.12 ; 52.18,26.66 C154.1 ; C154.1 52.18,27.83 ; C154.1 52.73,27.24 ; P15.8 14.48,23.49 ; 20.54,17.32 C146.1 ; C146.1 21.09,17.9 ; C146.1 21.09,16.73 ; P15.22 14.35,41.27 ; 62.42,24.17 C106.1 63.01,24.72 ; 109,37.85 C126.1 108.45,37.26 ; 109.8,42.92 C97.1 109.22,43.46 ; 83.12,58.8 C25.1 ; C25.1 82.18,57.72 ; C25.1 82.18,60.38 v1(82.11,60.45) 82.18,60.52 82.18,60.69 v1(82.68,61.19) ; 108.2,43.46 C124.1 107.62,42.92 ; 3.42,38.85 R150.1 3.42,37.6 ; 30.67,5.5 P29.1 27.95,5.5 ; 50.16,44.18 R190.1 50.73,43.56 ; 170.42,42.04 P10.1 170.42,44.15 ; D10.A v1(158.75,40.47) ; 103.86,35.94 C128.1 104.4,36.53 ; 11.55,20.65 C152.2 12.1,20.07 ; 45.47,53.46 P8.9 47.24,53.46 ; 11.55,24.56 C141.2 12.1,25.15 ; R216.1 v1(43.95,20.82) ; R159.1 v1(87.7,62.93) ; 41.53,13.53 U17.4 ; P15.10 14.48,26.03 ; 32.33,40.89 R178.1 32.9,40.27
  vias: v1(3.64,1.52) v1(3.68,41.59) v1(4.06,68.96) v1(6.18,1.52) v1(6.6,68.96) v1(7.02,41.62) v1(7.87,16.95) v1(8.72,1.52) v1(9.14,68.96) v1(10.03,23.11) v1(10.1,21.97) v1(10.86,23.11) v1(10.86,21.97) v1(10.86,21.15) v1(11.26,1.52) v1(11.68,68.96) v1(11.68,23.11) v1(11.68,21.97) v1(11.68,21.15) v1(13.21,58.29) v1(13.21,57.53) v1(13.21,56.77) v1(13.8,1.52) v1(14.22,68.96) v1(16.34,1.52) v1(16.76,68.96) v1(17.84,68.52) v1(17.84,63.44) v1(18.73,68.52) v1(18.73,63.44) v1(18.88,1.52) v1(19.3,68.96) v1(21.42,1.52) v1(21.59,46.99) v1(21.84,68.96) v1(22.16,25.97) v1(22.86,57.4) v1(23.24,12.06) v1(23.62,57.4) v1(24.26,26.67) v1(24.38,57.4) v1(25.15,57.4) v1(26.5,1.52) v1(26.92,68.96) v1(27.71,42.21) v1(27.71,41.32) v1(27.71,40.44) v1(27.71,39.55) v1(27.71,38.66) v1(27.81,30.61) v1(28.45,30.61) v1(28.6,42.21) v1(28.6,41.32) v1(28.6,40.44) v1(28.6,39.55) v1(28.6,38.66) v1(29.04,1.52) v1(29.08,30.61) v1(29.46,68.96) v1(29.49,42.21) v1(29.49,41.32) v1(29.49,40.44) v1(29.49,39.55) v1(29.49,38.66) v1(29.59,26.67) v1(30.38,42.21) v1(30.38,41.32) v1(30.38,40.44) v1(30.38,39.55) v1(30.38,38.66) v1(30.99,68.96) v1(30.99,68.07) v1(30.99,12.32) v1(31.12,30.61) v1(31.27,42.21) v1(31.27,41.32) v1(31.27,40.44) v1(31.27,39.55) v1(31.27,38.66) v1(31.58,1.52) v1(31.75,30.61) v1(32,68.96) v1(32.16,41.32) v1(32.16,40.44) v1(32.38,30.61) v1(32.64,18.8) v1(34.54,68.96) v1(36.2,12.19) v1(36.51,26.67) v1(36.66,1.52) v1(37.08,68.96) v1(37.34,12.06) v1(38.23,29.46) v1(39.62,68.96) v1(41.74,1.52) v1(42.16,68.96) v1(42.55,25.4) v1(42.8,29.84) v1(42.8,29.21) v1(43.31,13.53) v1(43.94,29.84) v1(43.94,29.21) v1(44.28,1.52) v1(44.58,29.84) v1(44.58,29.21) v1(45.66,18.92) v1(46.82,1.52) v1(47.05,27.37) v1(47.24,68.96) v1(47.18,38.35) v1(47.75,29.02) v1(47.76,28.28) v1(47.76,27.51) v1(47.88,34.67) v1(47.88,19.56) v1(48.2,43.43) v1(48.53,29.04) v1(48.53,28.28) v1(49.02,19.56) v1(49.28,49.02) v1(49.66,34.67) v1(49.78,68.96) v1(49.78,16.26) v1(50.04,1.52) v1(50.16,58.8) v1(50.16,58.04) v1(50.16,44.51) v1(50.16,32.26) v1(50.16,30.35) v1(50.55,47.94) v1(50.8,18.86) v1(51.05,58.8) v1(51.05,58.04) v1(51.05,57.28) v1(52.32,68.96) v1(52.64,26.48) v1(53.4,36.64) v1(53.78,61.91) v1(54.86,68.96) v1(54.93,32.7) v1(55.31,44.01) v1(55.5,39.12) v1(55.88,55.75) v1(55.88,20.95) v1(56.01,44.01) v1(56.26,36.64) v1(56.71,55.75) v1(57.09,37.72) v1(57.4,68.96) v1(57.79,20.7) v1(57.79,19.94) v1(58.67,32.7) v1(58.86,15.18) v1(59.12,55.82) v1(59.12,18.8) v1(59.69,43.05) v1(59.69,37.85) v1(59.94,68.96) v1(59.88,55.82) v1(60.9,30.35) v1(61.09,62.17) v1(61.09,61.15) v1(61.09,60.58) v1(61.09,35.05) v1(61.28,55.75) v1(61.39,34.08) v1(61.39,33.32) v1(61.39,32.56) v1(61.85,63.5) v1(61.96,47.48) v1(61.96,46.72) v1(61.96,45.96) v1(62.15,34.08) v1(62.15,33.32) v1(62.17,32.58) v1(62.23,55.75) v1(62.42,23.94) v1(62.42,20.83) v1(62.48,68.96) v1(62.73,47.48) v1(62.73,46.72) v1(62.74,45.97) v1(62.8,34.1) v1(63.25,24.64) v1(63.2,15.96) v1(63.56,32.51) v1(64.64,42.92) v1(66.42,65.66) v1(66.42,64.77) v1(66.41,63.88) v1(66.99,18.35) v1(66.99,15.81) v1(67.06,10.54) v1(67.56,68.96) v1(67.56,65.66) v1(67.56,64.77) v1(67.56,63.88) v1(68.71,65.66) v1(68.71,64.77) v1(68.71,63.88) v1(68.96,20.7) v1(68.96,19.94) v1(69.06,10.53) v1(70.1,68.96) v1(72.64,68.96) v1(73.53,65.53) v1(73.53,64.64) v1(73.79,22.16) v1(74.29,42.93) v1(74.8,65.53) v1(74.8,64.64) v1(75.18,68.96) v1(75.95,65.53) v1(75.95,64.64) v1(77.09,65.53) v1(77.09,64.64) v1(77.3,1.52) v1(78.36,1.52) v1(79.25,47.62) v1(79.84,1.52) v1(80.14,14.86) v1(80.96,57.78) v1(81.79,57.78) v1(82.11,62.1) v1(82.11,61.21) v1(82.38,1.52) v1(82.68,62.1) v1(82.68,60.45) v1(82.8,68.96) v1(83.25,62.1) v1(83.25,61.21) v1(83.25,60.45) v1(83.44,57.85) v1(84.26,57.85) v1(84.2,42.93) v1(84.33,17.14) v1(84.92,1.52) v1(85.34,68.96) v1(86.36,46.1) v1(86.61,64.9) v1(86.99,55.56) v1(87.46,1.52) v1(87.88,68.96) v1(89.34,56.01) v1(90,1.52) v1(90.42,68.96) v1(90.42,56.01) v1(91.31,65.02) v1(91.31,63.88) v1(92.54,1.52) v1(93.85,40.51) v1(93.98,15.24) v1(94.74,65.02) v1(94.74,63.88) v1(95.08,1.52) v1(95.5,68.96) v1(95.88,65.02) v1(95.88,63.88) v1(97.15,65.02) v1(97.15,63.88) v1(97.62,1.52) v1(98.04,68.96) v1(98.42,65.02) v1(98.42,63.88) v1(99.44,44.7) v1(100.14,44.7) v1(100.16,1.52) v1(100.58,68.96) v1(100.9,44.7) v1(100.96,15.24) v1(101.28,60.9) v1(102.7,1.52) v1(103.12,68.96) v1(103.25,62.86) v1(105.24,1.52) v1(105.66,68.96) v1(107.31,62.86) v1(107.31,43.31) v1(107.31,42.67) v1(107.78,1.52) v1(108.2,68.96) v1(108.2,36.96) v1(108.2,36.07) v1(108.2,35.18) v1(108.84,54.86) v1(109.09,35.18) v1(109.09,34.29) v1(109.22,60.96) v1(109.6,54.86) v1(109.94,36.96) v1(109.94,36.07) v1(109.94,35.18) v1(109.94,34.29) v1(109.94,33.41) v1(110.32,1.52) v1(110.74,68.96) v1(110.87,47.37) v1(110.87,46.61) v1(110.87,45.85) v1(110.81,36.96) v1(110.81,36.07) v1(110.81,35.18) v1(110.81,34.29) v1(111.57,61.91) v1(111.7,35.18) v1(112.86,1.52) v1(113.03,61.91) v1(113.28,68.96) v1(115.44,65.47) v1(115.4,1.52) v1(115.82,68.96) v1(117.6,30.5) v1(117.78,40.48) v1(117.94,1.52) v1(118.36,68.96) v1(118.55,67.95) v1(118.49,29.61) v1(118.68,41.38) v1(119.39,28.71) v1(119.58,42.28) v1(119.71,32.09) v1(119.94,38.94) v1(120.29,27.81) v1(120.48,43.17) v1(120.48,1.52) v1(120.61,31.2) v1(120.84,39.83) v1(120.9,68.96) v1(121.19,26.91) v1(121.37,44.07) v1(121.51,30.3) v1(121.74,40.73) v1(121.98,61.02) v1(122.05,59.75) v1(122.11,26.04) v1(122.3,66.99) v1(122.32,44.92) v1(122.41,29.4) v1(122.64,41.63) v1(123.02,1.52) v1(123.26,25.5) v1(123.3,28.5) v1(123.44,68.96) v1(123.5,45.39) v1(123.53,42.53) v1(124.48,28.02) v1(124.53,25.4) v1(124.77,45.44) v1(124.77,42.82) v1(125.56,1.52) v1(125.75,28.02) v1(125.8,25.4) v1(125.98,68.96) v1(126.04,45.44) v1(126.04,42.82) v1(126.24,36.2) v1(126.24,35.43) v1(126.24,34.67) v1(126.87,36.2) v1(126.87,35.43) v1(126.87,34.67) v1(127.02,28.02) v1(127.07,25.4) v1(127.31,45.44) v1(127.31,42.82) v1(128.1,1.52) v1(128.29,28.02) v1(128.34,25.4) v1(128.52,68.96) v1(128.58,45.44) v1(128.58,42.82) v1(128.75,46.2) v1(128.75,28.78) v1(128.82,42.07) v1(128.82,24.65) v1(129.64,46.2) v1(129.64,28.78) v1(129.71,42.07) v1(129.71,24.65) v1(130.64,1.52) v1(131.06,68.96) v1(132.82,46.2) v1(132.88,42.07) v1(132.97,28.83) v1(132.88,24.65) v1(133.18,1.52) v1(133.6,68.96) v1(133.98,46.23) v1(133.98,42.04) v1(133.98,28.83) v1(133.98,24.64) v1(135.34,28.78) v1(135.38,46.2) v1(135.42,24.65) v1(135.56,42.07) v1(135.72,1.52) v1(136.14,68.96) v1(136.65,46.2) v1(136.61,28.78) v1(136.69,24.65) v1(136.83,42.07) v1(137.92,46.2) v1(137.88,28.78) v1(137.96,24.65) v1(138.1,42.07) v1(138.26,1.52) v1(138.68,68.96) v1(139.15,28.78) v1(139.19,46.2) v1(139.23,24.65) v1(139.37,42.07) v1(140.46,46.2) v1(140.42,28.78) v1(140.5,24.65) v1(140.64,42.07) v1(140.8,1.52) v1(141.22,68.96) v1(141.73,46.2) v1(141.69,28.78) v1(141.77,24.65) v1(141.91,42.07) v1(142.96,28.78) v1(143,46.2) v1(143.04,24.65) v1(143.18,42.07) v1(143.34,1.52) v1(143.76,68.96) v1(144.27,46.2) v1(144.45,42.07) v1(145.54,46.2) v1(145.67,37.08) v1(145.72,42.07) v1(145.91,5.32) v1(145.92,4.06) v1(145.88,1.52) v1(146.3,68.96) v1(146.56,3.49) v1(146.81,46.2) v1(146.99,42.07) v1(147.83,28.83) v1(147.95,24.64) v1(148.08,46.2) v1(148.26,42.07) v1(148.42,1.52) v1(148.84,68.96) v1(149.35,46.2) v1(149.31,28.78) v1(149.39,24.65) v1(149.53,42.07) v1(150.62,46.2) v1(150.58,28.78) v1(150.66,24.65) v1(150.8,42.07) v1(150.96,1.52) v1(151.38,68.96) v1(152.61,28.78) v1(152.7,24.65) v1(153.5,1.52) v1(153.92,68.96) v1(153.88,28.78) v1(153.97,24.65) v1(155.15,28.78) v1(155.24,24.65) v1(155.7,46.2) v1(155.88,42.07) v1(156.04,1.52) v1(156.33,46.2) v1(156.46,68.96) v1(156.51,42.07) v1(156.51,24.65) v1(156.97,46.2) v1(157.15,42.07) v1(157.78,24.65) v1(157.92,12) v1(157.92,11.37) v1(157.92,10.73) v1(158.56,12) v1(158.56,11.37) v1(158.56,10.73) v1(158.58,1.52) v1(159,68.96) v1(159.05,24.65) v1(159.19,12) v1(159.19,11.37) v1(159.19,10.73) v1(160.32,25.41) v1(160.32,24.65) v1(160.78,45.47) v1(160.78,42.8) v1(161.12,1.52) v1(161.54,68.96) v1(161.54,56.13) v1(161.54,55.37) v1(161.8,45.47) v1(161.81,42.82) v1(161.92,24.51) v1(162.43,56.13) v1(162.43,55.37) v1(163.07,45.47) v1(163.08,42.82) v1(163.66,1.52) v1(163.83,56.9) v1(163.83,56.13) v1(163.83,55.37) v1(164.08,68.96) v1(164.21,46.48) v1(164.35,42.83) v1(165.1,41.02) v1(165.23,47.5) v1(165.25,43.73) v1(166.14,44.62) v1(166.2,1.52) v1(166.39,48.28) v1(166.62,68.96) v1(167.04,45.52) v1(167.66,48.28) v1(168.3,45.66) v1(168.74,1.52) v1(168.93,48.28) v1(169.16,68.96) v1(169.57,45.61) v1(169.99,37.53) v1(170.2,48.28) v1(171.28,1.52) v1(171.7,68.96) v1(173.82,1.52) v1(174.24,68.96) v1(176.28,67.44) v1(176.28,64.9) v1(176.28,8.76) v1(176.28,7.25) v1(176.28,4.71) v1(176.28,2.17)
